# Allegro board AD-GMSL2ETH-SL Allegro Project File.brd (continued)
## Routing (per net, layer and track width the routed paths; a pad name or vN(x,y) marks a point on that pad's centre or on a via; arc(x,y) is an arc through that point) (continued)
3V3: length 198.8
  TOP w0.203: 85.61,53.7 85.65,53.75 U8.A2
  TOP w0.254: 85.59,53.72 C144.1
  TOP w0.279: v1(143.34,22.37) 143.34,21.98 143.04,21.68 U13.15 ; U12.15 v1(143.06,99.44)
  TOP w0.305: v1(120.42,22.91) 120.41,22.93 C124.1 U25.8 ; v1(12.37,40.65) 14.4,38.62 v1(18.74,38.62) ; 85.61,53.7 85.59,53.72 85.59,55.16 86.62,56.19 88.07,56.19 89.82,57.94 107.66,57.94 112.5,62.78 119.25,62.78 120.57,64.1 v1(120.57,65.23) ; v1(118.06,66.67) 118.04,66.69 C115.1 U20.8 ; U3.34 v1(95.11,111.23)
  TOP w0.356: v2(75.69,93.98) P3.B13 P3.B14 ; v1(95.11,111.23) C111.1 ; v1(72.06,17.88) 71.1,17.88 C156.1
  TOP w0.483: R45.1 v1(96.1,113.18) ; R56.1 v1(118.06,66.67) ; R38.1 v1(90.04,111.15) ; v1(135.95,64.96) R81.1 R83.1 R80.1 ; R155.1 v1(117.27,21.82) ; R42.1 93.54,112.4 93.37,112.57 92.45,112.57 R40.1 v1(91.71,112.82) ; v1(138.83,54.26) R127.1 R133.1 R184.1 R203.1 R179.1 R183.1 ; R124.1 v1(114.91,65.58) ; R82.1 v1(141.91,62.3) ; v1(120.42,22.91) R69.1
  TOP w0.508: v1(19.5,37.86) v1(19.5,38.62) v1(18.74,38.62) ; v1(19.5,37.86) v1(18.74,37.86) v1(18.74,38.62) ; v1(19.5,37.86) v1(18.74,38.62) ; DS9.A v1(120.66,14.96) ; R248.1 122.7,19.25 v1(121.72,19.25) ; DS6.A v1(105.3,14.96) ; DS10.A v1(128.33,14.96) ; DS8.A v1(112.97,14.96)
  TOP w0.61: D9.2 20.28,79.77 D16.2 23.19,78.74 23.19,78.74 v1(23.32,78.74) ; D25.2 v1(19.29,57.73) ; D19.2 22.33,87.65 v1(23.32,86.66) ; D23.2 v1(19.29,54.58) ; D10.2 20.35,82.92 21.31,81.97 D17.2 v1(23.31,81.35) ; D20.2 v1(19.35,65.6) ; v1(23.32,84.63) 23.18,84.5 D18.2 21.31,85.12 20.35,86.07 D11.2 ; D22.2 19.37,68.75 19.87,68.25 21.31,68.25 ; D7.2 19.44,71.9 19.94,71.4 21.31,71.4 ; 23.32,68.25 21.31,68.25 ; 21.31,68.25 D21.2 ; v1(23.32,76.08) 23.32,76.08 D15.2 ; D8.2 19.21,75.05 19.82,74.44 20.35,74.44 D14.2 23.32,73.47 ; 21.31,71.4 D24.2 ; 21.31,71.4 23.32,71.4 ; D12.2 v1(19.35,89.22)
  TOP w0.889: v1(23.32,86.66) v1(23.32,84.63) 23.32,81.35 v1(23.31,81.35) 23.32,81.35 v1(23.32,78.74) v1(23.32,76.08) v1(23.32,72.31) v1(23.32,69.22) v1(23.32,66.07)
  BOTTOM w0.203: 141.86,55.29 U7.A2 ; v1(72.06,17.88) U22.A3
  BOTTOM w0.305: C147.1 13.18,41.28 R74.1 v1(12.37,40.65) ; 90.04,117.51 C119.1 91.06,117.51 91.22,117.68 U15.8
  BOTTOM w0.483: R48.1 v1(89.92,114.73) ; 141.86,55.29 C143.1 v1(143.56,55.29) ; v1(89.59,117.51) 90.04,117.51
  BOTTOM w0.508: C257.1 v1(64.18,18.08) P9.4 ; 75.69,91.46 v2(75.69,93.98) ; R61.1 R59.1 31.33,24.68 30.16,25.84 R146.1 v1(28.43,25.84) 28.35,25.93 R150.1 v1(27.71,26.7) R147.1 ; R148.1 v1(28.35,19.79) ; C256.1 v1(72.06,17.88)
  BOTTOM w0.762: 75.69,91.46 74.93,90.7 66.35,90.7 64.72,92.33 64.72,101.27 66.33,102.88 v1(66.33,109.01) v1(66.33,109.91)
  vias: v1(48.89,25.54) v1(48.89,24.77) v1(49.65,25.54) v1(49.65,24.77) v1(144.78,19.48) v1(145.06,96.52)
3V3_FT232R: length 18.5
  TOP w0.305: v1(86.51,16.59) 86.78,16.32 C262.1 U24.1 ; U24.4 v1(86.78,12.94)
  TOP w0.356: v1(86.78,12.94) 86.41,12.57 v1(85.67,12.57) 85.66,12.55 85.66,10.68 84.09,9.12 v1(80.91,9.12)
  L5_PWR w0.356: v1(86.51,16.59) 86.51,13.2 v1(86.78,12.94)
  BOTTOM w0.305: U23.1 C258.1 85.45,12.79 v1(85.67,12.57) ; v1(80.91,9.12) 80.91,9.75 ; 80.91,9.75 80.92,9.75 C261.1 ; 80.91,9.75 U23.8
3V3_SFP_RX: length 13.5
  BOTTOM w0.508: 41.2,23.39 39.85,24.74 v1(39.6,24.74) C2.1
  BOTTOM w0.762: 41.2,23.39 42.49,23.39 43.26,22.63 43.26,21.17 43.76,20.66 C254.1
  BOTTOM w0.889: L10.2 47.16,19.31 45.81,20.66 C254.1
3V3_SFP_TX: length 13.7
  BOTTOM w0.508: C3.1 v1(39.6,25.54) 39.89,25.54 40.87,26.52
  BOTTOM w0.762: 40.87,26.52 42.49,26.52 43.26,27.28 43.26,29.15 43.76,29.65 C1.1
  BOTTOM w0.889: C1.1 45.81,29.65 47.16,31.01 L11.2
3V8: length 13.9
  TOP w0.305: v1(30.15,40.64) 30.15,40.61 32.15,38.62 v1(36.52,38.62)
  TOP w0.508: v1(36.52,38.62) v1(36.52,37.86) v1(37.28,37.86) ; v1(36.52,38.62) v1(37.28,37.86) ; v1(36.52,38.62) v1(37.28,38.62) v1(37.28,37.86)
  BOTTOM w0.305: C146.1 30.96,42.21 R229.1 v1(30.15,40.64)
  vias: v1(120.42,117.97) v1(120.42,117.2) v1(121.18,117.97) v1(121.18,117.2)
5V: length 140.7
  TOP w0.254: R109.2 v1(34.24,71.7)
  TOP w0.305: R220.1 45.32,51.33 v1(45.34,51.35) C271.1 46.47,51.35 46.78,51.04 U26.5
  TOP w0.356: R101.1 50.32,57.54 P6.2
  TOP w0.483: R29.1 v1(74.96,106.72) ; R100.1 v1(24.82,90.12) ; R112.1 v1(25.74,85.88)
  TOP w0.508: DS11.A v1(132.53,14.96)
  TOP w0.61: D6.2 v1(21.31,57.44)
  L5_PWR w0.508: 49.5,55.64 P6.2 ; P6.2 49.5,57.8 ; P6.2 48.43,56.72 ; P6.2 50.58,56.72
  BOTTOM w0.254: v1(34.24,71.7) R111.1
  BOTTOM w0.508: v1(39.04,39.8) 39.88,39.8 40.39,39.29 40.39,36.55 42.88,34.06 53.16,34.06 58.67,39.57 83.67,39.57 86.18,37.06 86.18,20.47 90.3,16.36 131.13,16.36 v1(132.53,14.96)
  BOTTOM w0.889: P6.2 50.91,56.72 D1.C
  vias: v1(19.73,44.97) v1(19.73,44.21) v1(20.49,44.97) v1(20.49,44.21) v1(28.62,44.97) v1(28.62,44.21) v1(29.38,44.97) v1(29.38,44.21) v1(31.75,76.15) v1(31.75,75.39) v1(31.75,74.63) v1(31.75,73.86) v1(32.51,76.15) v1(32.51,75.39) v1(32.51,74.63) v1(32.51,73.86) v1(37.51,44.97) v1(37.51,44.21) v1(38.27,44.97) v1(38.27,44.21) v1(46.4,44.97) v1(46.4,44.21) v1(47.16,44.97) v1(47.16,44.21) v1(110.24,95.07) v1(110.24,94.37)
5V_BIAS: length 4.2
  TOP w0.305: U10.13 31.2,84.85 v1(30.99,84.63) 30.67,84.32 C228.1
  TOP w0.483: R93.1 v1(31.03,92.69) ; R110.2 v1(25.74,86.66) ; R96.1 v1(33.15,92.68)
5V_SYNCOUT: length 47.6
  TOP w0.305: U10.2 31.7,89.36 v1(31.7,90.55)
  TOP w0.483: R240.2 v1(42.44,51.05)
  L8_SIG w0.508: v1(42.44,51.05) 37.36,56.13 37.36,64.83 29.44,72.75 29.44,88.29 v1(31.7,90.55)
9V_FB: length 10.9
  TOP w0.305: v1(39.02,52.26) U21.18
  BOTTOM w0.508: v1(44.83,60.02) 39.02,54.21 v1(39.02,52.26)
GND: length 2443
  TOP w0.203: 73.48,17.32 73.76,17.6 v5(73.76,18.08) 73.76,18.64 ; v3(73.15,28.9) 73.15,28.88 ; 87.64,55.09 87.63,55.08
  TOP w0.254: P5.C10 73.78,27.78 73.76,27.76 ; P5.C10 v4(74.1,28.95) P5.D11 74.42,30.17 74.37,30.22 ; P5.C10 P5.C9 ; 89.63,30.23 89.66,30.2 P5.D35 P5.C34 89.02,27.85 88.94,27.76 ; v2(88.13,95.58) P3.C33 88.39,94.57 88.39,94.57 ; 80.13,26.41 P5.B20 80.13,27.36 80.14,27.37 ; 80.13,26.41 v2(80.45,26.41) ; 80.13,26.41 79.82,26.41 P5.A19 79.5,25.31 ; 83.25,27.94 83.31,28 P5.C25 v2(83.63,28.95) P5.D26 83.94,30.06 83.92,30.09 ; 83.25,27.94 83.66,27.94 83.7,27.9 ; 83.25,27.94 v2(82.37,27.94) 82.37,27.39 v2(82.36,27.37) P5.B23 v2(81.72,26.41) P5.A22 ; 90.93,93.05 91.18,93.05 v2(91.24,92.99) P3.A37 ; 90.93,93.05 P3.A37 ; 90.93,93.05 89.66,93.05 ; P5.B8 72.51,27.46 72.51,27.47 ; P5.B8 v3(72.83,26.41) P5.A9 ; P5.B8 P5.B7 ; P3.A57 v2(103.63,91.96) ; P3.A57 P3.A58 ; P3.A57 P3.B56 ; P3.B48 v2(97.91,94.09) ; P3.B48 P3.A49 ; P3.B48 P3.B47 ; P3.A37 90.93,92.04 ; P5.D43 94.74,29.43 v3(94.74,28.96) 94.74,28.95 P5.C43 94.74,27.91 94.73,27.91 ; P3.C37 v2(90.93,94.6) ; 89.66,93.94 P3.B35 89.66,93.05 ; P5.C5 P5.C6 71.25,28.48 v4(71.25,28.9) 71.53,28.9 P5.D7 ; v3(97.28,29.92) 97.28,29.92 P5.D47 ; P5.A9 73.05,25.84 73.05,25.35 v4(73.07,25.34) ; P5.A9 P5.A10 ; P3.C54 v2(101.72,94.5) ; P3.C54 P3.D55 ; P3.C54 P3.C53 ; 72.49,94.55 72.51,94.57 P3.C8 P3.D9 v2(73.15,96.63) ; 85.24,25.34 85.21,25.37 P5.A28 v2(85.53,26.41) P5.B29 85.85,27.46 85.87,27.47 ; v2(73.15,94.09) P3.B9 P3.A8 v2(72.51,91.96) ; v2(76.35,91.95) 76.32,91.98 P3.A14 P3.B15 v3(76.96,93.99) ; 82.04,92.96 82.04,92.96 P3.B23 ; 82.04,92.96 v2(80.77,92.96) P3.A21 ; 82.04,92.96 83.95,92.96 ; P5.A10 73.78,25.44 73.61,25.27 ; P5.A10 v2(74.1,26.41) P5.B11 74.42,27.34 74.21,27.54 ; 103.7,25.22 103.63,25.28 P5.A57 ; 78.23,27.49 P5.B17 v4(77.91,26.41) P5.A16 77.59,25.55 v4(77.77,25.37) ; 96.01,26.41 94.75,26.41 94.74,26.42 ; 96.01,26.41 v2(96.33,26.41) 97.12,26.41 97.28,26.57 97.28,26.57 P5.B47 97.28,27.41 97.36,27.49 ; 96.01,26.41 96.01,26.41 P5.A45 96.01,25.37 95.99,25.35 ; P3.A49 v2(98.55,91.96) ; P3.A49 P3.A50 ; P5.C9 v3(73.15,28.9) 72.87,28.9 P5.D8 ; P5.C9 73.15,28.88 ; P5.C9 73.15,27.73 73.17,27.71 ; P3.B39 92.2,93.95 v2(92.04,94.1) ; 83.94,92.96 P3.A26 v2(83.94,91.96) ; 83.95,92.96 84.25,92.96 84.58,93.29 P3.B27 v2(84.58,94.09) ; 90.94,25.23 90.93,25.24 P5.A37 P5.B38 91.56,27.5 91.67,27.6 ; 94.74,26.42 P5.A43 94.74,25.38 94.66,25.3 ; 94.74,26.42 P5.B43 ; 94.74,26.42 94.73,26.41 93.47,26.41 ; v2(96.64,94.5) P3.C46 P3.D47 ; P5.D8 72.51,30.1 72.51,30.11 ; P5.D8 P5.D7 ; P3.A54 v2(101.72,91.96) ; P3.A54 P3.A53 ; P3.A54 P3.B55 ; P5.B7 71.88,27.44 71.89,27.45 ; P5.B7 71.53,26.36 v3(71.25,26.36) 71.24,26.35 P5.A6 ; P3.D43 94.74,96.58 v2(94.69,96.64) ; P5.A5 v3(70.29,26.41) P5.B4 P5.B3 ; P5.A5 70.61,25.23 ; P5.A5 P5.A6 ; v4(75.37,27.99) P5.C13 P5.D14 v2(76.32,29.86) ; v2(104.9,96.63) P3.D59 P3.C58 ; v2(74.24,91.94) 74.42,92.12 P3.A11 P3.B12 v2(75.05,93.99) ; P3.C53 v2(101.09,94.5) ; P3.C53 P3.D52 ; v2(79.5,96.63) P3.D19 79.5,95.81 79.75,95.56 80.77,95.56 ; P3.B51 P3.B52 ; P3.B51 P3.A50 ; P3.B51 v2(99.82,94.09) ; P3.B52 v2(100.45,94.09) ; P3.B52 P3.A53 ; P3.A50 v2(99.18,91.96) ; P5.C1 P5.C2 v4(69.02,28.95) P5.D3 ; 103.59,27.88 103.63,27.92 P5.C57 103.63,28.7 103.38,28.96 102.69,28.96 102.36,29.29 P5.D55 102.36,30.05 102.19,30.22 ; 83.91,27.53 83.94,27.5 P5.B26 v2(83.63,26.41) P5.A25 83.31,25.24 83.32,25.23 ; 98.54,27.86 98.55,27.86 P5.C49 v2(98.87,28.95) ; P3.C49 v2(98.55,94.5) ; P3.C49 P3.C50 ; P3.C49 P3.D48 ; 87.08,27.66 87.12,27.7 P5.C31 87.47,29 v3(87.75,29) 87.75,29.42 P5.D32 87.75,30.04 87.82,30.11 ; P3.C57 v2(103.63,94.5) ; P3.C57 P3.D56 ; P3.C57 P3.C58 ; P3.C50 v2(99.18,94.5) ; P3.C50 P3.D51 ; P3.D51 v2(99.82,96.63) ; P3.D51 P3.D52 ; P5.D3 69.34,30.13 69.31,30.16 ; P5.D3 P5.D4 69.97,29.98 70.06,30.06 ; P3.D52 v2(100.45,96.63) ; v2(96.01,91.96) P3.A45 P3.A46 ; P3.C29 v2(85.85,94.6) ; P5.D7 71.88,30.04 71.87,30.05 ; P5.A53 v2(101.41,25.45) ; 89.69,27.54 89.66,27.5 P5.B35 P5.A34 89.02,25.3 89.16,25.17 ; P5.C45 96.01,27.99 v3(95.99,27.97) ; v2(70.61,91.96) P3.A5 P3.B6 v2(71.24,93.99) ; P3.D56 v2(102.99,96.63) ; P3.D56 P3.D55 ; P5.B51 v3(100.31,27.63) 101.09,27.63 v3(101.09,27.64) 102.06,27.64 102.36,27.33 P5.B55 ; 74.36,94.54 74.42,94.6 P3.C11 P3.D12 v2(75.05,96.71) ; U8.A3 86.82,54.15 86.7,54.27 ; P3.A58 P3.B59 v2(104.9,93.99) ; P3.A58 v2(104.26,91.96) ; 69.37,94.24 69.34,94.2 P3.B3 P3.A2 v2(68.7,91.96) ; P3.D47 P3.D48 ; P3.D47 v2(97.28,96.63) ; P3.D48 v2(97.91,96.63) ; P3.D55 v2(102.36,96.63) ; P5.A6 71.24,25.39 ; P3.D27 v2(84.58,96.63) ; P3.A46 v2(96.64,91.96) ; P3.A46 P3.B47 ; P3.C2 68.7,94.52 68.74,94.49 ; P3.C2 P3.C1 v2(68.07,94.6) ; P3.C2 P3.D3 69.34,96.62 69.3,96.67 ; v2(81.09,27.99) P5.C22 P5.D23 82.04,29.94 82.17,30.07 ; P3.D35 v2(89.66,96.63) ; v2(76.96,96.63) P3.D15 P3.C14 v2(76.32,94.6) ; P3.C58 v2(104.26,94.5) ; v2(79.82,27.99) P5.C19 v2(79.82,28.95) P5.D20 80.13,30.01 80.07,30.08 ; 85.83,30.03 85.85,30.01 P5.D29 v2(85.53,28.95) P5.C28 85.21,27.75 85.15,27.69 ; 87.29,25.24 87.12,25.41 P5.A31 v2(87.44,26.41) P5.B32 87.75,27.65 87.84,27.73 ; P3.B56 v2(102.99,94.09) ; P3.B56 P3.B55 ; 80.77,95.56 81.79,95.56 82.04,95.81 P3.D23 ; 80.77,95.56 P3.C21 ; P3.D39 v2(92.2,96.63) ; 68.7,25.22 68.7,25.23 P5.A2 P5.A1 68.07,25.33 68.02,25.27 ; 93.44,30.16 93.47,30.13 P5.D41 P5.C40 92.83,27.62 92.84,27.61 ; P3.B31 v2(87.12,94.09) ; P5.A49 v2(98.87,25.45) ; 70.6,94.53 70.61,94.55 P3.C5 P3.D6 v2(71.24,96.63) ; P3.B47 v2(97.28,94.09) ; 93.47,26.41 93.09,26.41 92.83,26.16 P5.A40 92.83,25.1 92.78,25.05 ; 93.47,26.41 P5.B41 93.47,27.45 93.33,27.58 ; 89.66,93.05 88.9,93.05 P3.A33 88.39,91.89 88.35,91.85 ; P3.B55 v2(102.36,94.09) ; P3.C25 v2(83.31,94.6) ; P3.B43 94.74,94.04 v2(94.7,94.09) ; v3(76.32,27.67) 76.32,27.67 P5.B14 v2(76.01,26.41) P5.A13 75.69,25.49 v2(75.47,25.26) ; 90.73,27.8 90.93,27.99 P5.C37 P5.D38 91.56,30.18 91.57,30.18 ; v2(78.86,91.96) P3.A18 P3.B19 ; P3.A53 v2(101.09,91.96) ; 93.47,91.84 P3.A41 ; 78.24,30.09 78.23,30.08 P5.D17 v2(77.91,28.95) P5.C16 77.59,27.67 v3(77.6,27.67) ; P3.D31 v2(87.12,96.63) ; P3.C41 v2(93.47,94.5) ; P5.D51 v3(99.82,29.92) 99.82,29.92 P5.D51
  TOP w0.305: C151.1 v2(106.55,108.33) ; C148.1 106.55,102.39 v2(106.25,102.69) ; 119.08,67.23 C115.2 C114.2 119.09,67.83 ; P5.A2 v3(69.02,26.41) P5.B3 ; U19.9 136.22,59.62 v1(135.97,59.87) ; 121.39,23.42 C124.2 C123.2 121.4,24.02
  TOP w0.356: 80.77,92.05 80.77,92.05 P3.A21 ; P5.C53 101.09,27.64 v3(101.09,27.64) ; P3.C17 v2(78.23,94.6) ; P3.D23 v2(82.04,96.63) ; C111.2 95.11,112.84
  TOP w0.406: 90.68,111.63 91.09,111.22 R39.2 R204.2 91.65,111.78 91.26,112.17 ; 52.29,51.05 R50.2 51.55,51.04 R51.2 50.09,51.04 v1(50.09,51.04) U26.2
  TOP w0.483: R97.2 v1(32.36,92.69) ; R43.1 v1(96.9,113.11) ; 134.72,64.95 134.72,64.95 R114.2 ; Y3.2 89.42,107.29 v1(89.79,107.29) C108.1 ; R99.2 v1(26.44,91.03) ; C227.2 v1(23.88,89.16) ; R237.2 v1(25.74,87.45) ; Y3.4 v1(87.98,104.6) 90.17,104.6 C107.2 ; R94.2 v1(30.25,92.69)
  TOP w0.508: P1.GND8 142.05,85.82 ; P1.GND8 142.05,82.61 ; P1.GND8 141.3,84.22 ; P1.GND8 142.8,84.22 ; J2.4 63.5,104.75 ; J2.4 64.77,103.48 ; J2.4 62.23,103.48 ; J2.4 63.5,102.21 ; 124.75,12.29 R66.2 ; R66.2 125.25,12.83 ; R66.2 124.75,13.36 ; 56.55,18.3 R251.2 ; R251.2 56.55,19.55 ; R251.2 55.98,18.92 ; P2.GND7 142.05,37.39 ; P2.GND7 141.3,35.78 ; P2.GND7 142.05,34.18 ; P2.GND7 142.8,35.78 ; P7.3 48.34,90.83 ; P7.3 48.34,89.33 ; P7.3 46.71,90.08 ; P7.3 49.96,90.08 ; 114.71,111.95 C225.2 ; C225.2 115.87,111.95 ; C225.2 115.29,111.4 ; 117.3,46.69 R176.2 116.73,46.06 ; 135.84,102.21 J3.4 ; J3.4 135.84,104.75 ; J3.4 134.57,103.48 ; J3.4 137.11,103.48 ; R85.2 89.18,55.78 ; R85.2 88.65,55.29 ; R85.2 89.71,55.29 ; C91.2 141.33,27.37 ; C91.2 142.38,26.47 ; C91.2 140.27,26.47 ; 138.1,91.94 C28.2 ; C28.2 139.15,91.03 ; C28.2 140.21,91.94 ; P7.11 49.96,82.08 ; P7.11 48.34,82.83 ; P7.11 48.34,81.33 ; P7.11 46.71,82.08 ; 122.72,113.39 C233.2 122.18,113.98 ; 2.93,51.61 P13.2 ; P13.2 5.09,51.61 ; P13.2 4.01,50.53 ; P13.2 4.01,52.69 ; 137.17,15.7 C89.2 ; C89.2 137.17,17.81 ; C89.2 136.27,16.76 ; 120.94,75.64 C22.2 121.84,76.69 ; R247.2 69.07,91.45 ; R247.2 69.64,90.82 ; R247.2 69.07,90.2 ; 109.54,32.05 R178.2 110.04,32.59 ; C88.2 139.99,26.47 ; C88.2 137.89,26.47 ; C88.2 138.94,27.37 ; 114.28,82.65 R2.1 ; R2.1 115.17,82.55 ; R2.1 115.07,83.44 ; R2.1 114.18,83.54 ; 117.28,49.07 C155.2 116.73,48.49 ; 53.55,56.26 R104.2 53.06,56.79 ; J1.5 80.01,103.48 ; J1.5 77.47,103.48 ; J1.5 78.74,104.75 ; J1.5 78.74,102.21 ; C65.2 120.94,44.62 ; C65.2 121.84,43.56 ; C65.2 120.94,42.51 ; 46.71,88.08 P7.5 ; P7.5 49.96,88.08 ; P7.5 48.34,87.33 ; P7.5 48.34,88.83 ; 144.5,37.18 P2.GND5 ; P2.GND5 144.5,38.68 ; P2.GND5 146.41,37.93 ; P2.GND5 142.6,37.93 ; C30.2 141.54,104.41 ; C30.2 140.48,103.51 ; C30.2 142.59,103.51 ; 109.41,19 R199.2 108.92,19.53 ; 58.42,102.21 J2.5 ; J2.5 57.15,103.48 ; J2.5 58.42,104.75 ; J2.5 59.69,103.48 ; R68.2 122.21,13.36 ; R68.2 122.71,12.83 ; R68.2 122.21,12.29 ; Y4.2 100.4,117.61 ; Y4.2 99.4,116.6 ; Y4.2 101.41,116.6 ; Y4.2 100.4,115.6 ; Q6.2 108.02,16.5 ; Q6.2 108.97,15.74 ; Q6.2 107.06,15.74 ; Q6.2 108.02,14.98 ; 137.48,77.72 P1.GND2 ; P1.GND2 138.75,76.45 ; P1.GND2 138.75,78.99 ; C7.2 120.94,86.04 ; C7.2 121.84,84.99 ; C7.2 120.94,83.94 ; P13.6 5.09,56.69 ; P13.6 4.01,57.77 ; P13.6 4.01,55.61 ; P13.6 2.93,56.69 ; 57.07,15.05 R149.2 57.61,15.54 ; 131.31,59.59 C235.2 130.81,60.12 ; 60.91,13.2 Q2.2 ; Q2.2 60.91,15.1 ; Q2.2 60.15,14.15 ; Q2.2 61.67,14.15 ; P7.9 49.96,84.08 ; P7.9 48.34,84.83 ; P7.9 46.71,84.08 ; P7.9 48.34,83.33 ; 142.14,13.08 R219.2 142.64,12.55 ; 33.34,113.17 R225.2 ; R225.2 34.58,113.17 ; R225.2 33.96,112.59 ; P6.1 49.5,55.26 ; P6.1 48.43,54.18 ; P6.1 50.58,54.18 ; P6.1 49.5,53.1 ; 115.52,102.21 J4.5 ; J4.5 116.79,103.48 ; J4.5 115.52,104.75 ; J4.5 114.25,103.48 ; C117.2 109.14,114 ; C117.2 108.61,113.5 ; C117.2 109.68,113.5 ; R169.2 116.53,88.39 ; P1.GND5 146.41,82.07 ; P1.GND5 142.6,82.07 ; P1.GND5 144.5,81.32 ; P1.GND5 144.5,82.82 ; Q12.2 115.71,16.5 ; Q12.2 114.76,15.74 ; Q12.2 116.66,15.74 ; Q12.2 115.71,14.98 ; C112.2 112.32,115.29 ; C112.2 111.79,114.79 ; C112.2 112.85,114.79 ; J2.3 63.5,109.83 ; J2.3 63.5,107.29 ; J2.3 62.23,108.56 ; J2.3 64.77,108.56 ; P2.GND2 138.75,34.85 ; P2.GND2 137.48,33.58 ; P2.GND2 138.75,32.31 ; 29.83,21.14 30.89,21.14 ; 30.89,21.14 30.89,20.5 ; 30.89,21.14 P4.10 ; P2.GND8 142.8,40.08 ; P2.GND8 141.3,40.08 ; P2.GND8 142.05,38.48 ; P2.GND8 142.05,41.68 ; 141.54,91.03 C29.2 ; C29.2 140.49,91.94 ; C29.2 142.6,91.94 ; 142.05,43.35 P2.GND10 142.05,41.8 ; P13.4 4.01,55.23 ; P13.4 4.01,53.07 ; P13.4 2.93,54.15 ; P13.4 5.09,54.15 ; 39.7,20.7 39.7,21.54 ; 39.7,21.54 41.05,21.54 ; 39.7,21.54 v1(39.6,21.54) ; 83.82,102.21 J1.4 ; J1.4 82.55,103.48 ; J1.4 85.09,103.48 ; J1.4 83.82,104.75 ; R95.2 29.96,92.59 ; R95.2 28.56,92.59 ; R95.2 29.26,93.15 ; R95.2 29.26,92.03 ; 82.55,108.56 J1.3 ; J1.3 85.09,108.56 ; J1.3 83.82,109.83 ; J1.3 83.82,107.29 ; P1.GND1 145.15,78.99 ; P1.GND1 146.42,77.72 ; P1.GND1 145.15,76.45 ; 122.18,111.71 C234.2 122.72,112.29 ; 97.18,97.89 C96.2 97.59,98.35 ; J3.3 135.84,109.83 ; J3.3 137.11,108.56 ; J3.3 135.84,107.29 ; J3.3 134.57,108.56 ; 119.33,103.48 J4.4 ; J4.4 120.6,102.21 ; J4.4 120.6,104.75 ; J4.4 121.87,103.48 ; C90.2 143.07,17.81 ; C90.2 143.97,16.76 ; C90.2 143.07,15.7 ; 118.18,111.33 R227.2 ; R227.2 118.68,110.79 ; R227.2 118.68,111.86 ; 115.52,107.29 J4.2 ; J4.2 114.25,108.56 ; J4.2 116.79,108.56 ; J4.2 115.52,109.83 ; R64.2 129.83,13.36 ; R64.2 130.33,12.83 ; R64.2 129.83,12.29 ; 114.53,114.79 C109.2 115.06,115.29 ; 77.47,108.56 J1.2 ; J1.2 78.74,107.29 ; J1.2 78.74,109.83 ; J1.2 80.01,108.56 ; 46.71,92.08 P7.1 ; P7.1 49.96,92.08 ; P7.1 48.34,91.33 ; P7.1 48.34,92.83 ; 145.32,18.36 R165.2 144.82,17.83 ; v1(128.27,59.34) R118.2 128.99,59.33 R116.2 ; C4.2 121.84,87.37 ; C4.2 120.94,88.42 ; C4.2 120.94,86.32 ; 141.3,79.92 P1.GND7 ; P1.GND7 142.8,79.92 ; P1.GND7 142.05,78.32 ; P1.GND7 142.05,81.52 ; P2.GND6 139.75,38.68 ; P2.GND6 141.5,37.93 ; P2.GND6 138,37.93 ; P2.GND6 139.75,37.18 ; 128.99,57.89 R116.2 ; R116.2 128.49,58.42 ; R23.1 115.17,38.42 ; R23.1 114.28,38.51 ; R23.1 114.18,39.4 ; R23.1 115.07,39.3 ; Q13.2 124.36,15.74 ; Q13.2 123.41,16.5 ; Q13.2 123.41,14.98 ; Q13.2 122.46,15.74 ; P2.GND3 146.42,42.28 ; P2.GND3 145.15,43.55 ; P2.GND3 145.15,41.01 ; J4.3 121.87,108.56 ; J4.3 120.6,109.83 ; J4.3 119.33,108.56 ; J4.3 120.6,107.29 ; 2.93,59.23 P13.8 ; P13.8 4.01,58.15 ; P13.8 5.09,59.23 ; P13.8 4.01,60.31 ; 138,82.07 P1.GND6 ; P1.GND6 139.75,82.82 ; P1.GND6 139.75,81.32 ; P1.GND6 141.5,82.07 ; C83.2 121.84,31.88 ; C83.2 120.94,30.83 ; C83.2 120.94,32.93 ; v1(39.6,23.94) 40.97,23.94 ; 129.49,103.48 J3.5 ; J3.5 130.76,104.75 ; J3.5 132.03,103.48 ; J3.5 130.76,102.21 ; 138.75,41.01 P2.GND4 ; P2.GND4 138.75,43.55 ; P2.GND4 137.48,42.28 ; P1.GND3 145.15,87.69 ; P1.GND3 145.15,85.15 ; P1.GND3 146.42,86.42 ; Q3.2 100.32,16.5 ; Q3.2 99.37,15.74 ; Q3.2 101.27,15.74 ; Q3.2 100.32,14.98 ; 48.34,79.33 P7.13 ; P7.13 48.34,80.83 ; P7.13 49.96,80.08 ; P7.13 46.71,80.08 ; 115.11,4.39 R67.2 115.65,3.9 ; 117.31,115.58 C118.2 ; C118.2 117.31,117.08 ; C118.2 118.03,116.33 ; 116.61,19.53 R201.2 117.11,19 ; 30.89,28.34 P4.1 ; 30.89,28.34 29.87,28.34 ; 30.89,28.34 30.89,28.98 ; 44.07,106.68 S12.3 ; S12.3 46.86,106.68 ; S12.3 45.47,105.28 ; S12.3 45.47,108.08 ; 58.42,107.29 J2.2 ; J2.2 57.15,108.56 ; J2.2 58.42,109.83 ; J2.2 59.69,108.56 ; C27.2 140.2,103.51 ; C27.2 138.1,103.51 ; C27.2 139.15,104.41 ; 30.92,115.42 31.5,115.42 31.5,114.8 ; 145.15,32.31 P2.GND1 ; P2.GND1 146.42,33.58 ; P2.GND1 145.15,34.85 ; 121.84,80.23 C152.2 120.94,81.28 ; 131.35,15.74 R206.2 130.82,16.23 ; 70.51,18.89 C156.2 71.09,19.44 ; 23.88,87.94 C227.2 23.35,88.45 ; C15.2 121.84,82.61 ; C15.2 120.94,81.56 ; C15.2 120.94,83.67 ; 48.34,85.33 P7.7 ; P7.7 46.71,86.08 ; P7.7 49.96,86.08 ; P7.7 48.34,86.83 ; 120.94,37.44 C154.2 121.84,36.39 ; 105.03,3.9 R63.2 104.5,4.39 ; P13.1 7.63,51.61 ; P13.1 6.55,50.53 ; P13.1 5.47,51.61 ; P13.1 6.55,52.69 ; 137.48,86.42 P1.GND4 ; P1.GND4 138.75,85.15 ; P1.GND4 138.75,87.69 ; v1(39.6,26.34) 41.1,26.34 ; P8.1 6.82,98.37 ; P8.1 4.41,98.37 ; P8.1 5.61,97.17 ; P8.1 5.61,99.58 ; 144.25,93.95 R157.2 ; R157.2 143.71,94.44 ; R157.2 144.78,94.44 ; 67.31,104.63 R30.2 ; R30.2 66.78,105.12 ; R30.2 67.84,105.12 ; R65.2 127.79,12.83 ; R65.2 127.29,12.29 ; R65.2 127.29,13.36 ; 142.05,34.07 P2.GND9 142.05,32.52 ; 122.1,73.12 R171.2 121.56,73.61 ; 130.76,107.29 J3.2 ; J3.2 129.49,108.56 ; J3.2 132.03,108.56 ; J3.2 130.76,109.83 ; C76.2 121.84,38.79 ; C76.2 120.94,37.74 ; C76.2 120.94,39.84 ; 115.89,92.33 C153.2 116.44,91.74 ; C68.2 120.94,42.25 ; C68.2 121.84,41.19 ; C68.2 120.94,40.14 ; 142.05,76.65 P1.GND9 142.05,78.2 ; D25.1 v1(19.29,56.73) ; 39.7,28.74 v1(39.6,28.74) ; 39.7,28.74 39.7,29.54 ; 39.7,28.74 41,28.74 ; 30.41,115.42 R222.2 29.84,114.8 ; R190.2 v1(91.74,101.74) ; 101.72,19 R152.2 101.22,19.53 ; 142.05,87.48 P1.GND10 142.05,85.93
  L2_GND w0.203: 73.75,18.82 73.76,18.81 v5(73.76,18.08) 73.76,17.57 73.69,17.5
  L2_GND w0.508: 78.74,102.21 J1.5 ; J1.5 77.47,103.48 ; J1.5 78.74,104.75 ; J1.5 80.01,103.48 ; 4.6,30.99 M4.GND12 ; M4.GND12 4.6,33.15 ; M4.GND12 3.52,32.07 ; M4.GND12 5.68,32.07 ; 31.08,32.07 M4.GND16 ; M4.GND16 33.12,32.07 ; M4.GND16 32.1,33.08 ; M4.GND16 32.1,31.05 ; 36.08,17.82 M4.GND5 ; M4.GND5 37.1,16.8 ; M4.GND5 37.1,18.83 ; M4.GND5 38.12,17.82 ; 138.75,41.01 P2.GND4 ; P2.GND4 138.75,43.55 ; P2.GND4 140.02,42.28 ; P2.GND4 137.48,42.28 ; 143.88,42.28 P2.GND3 ; P2.GND3 146.42,42.28 ; P2.GND3 145.15,41.01 ; P2.GND3 145.15,43.55 ; M4.GND18 37.1,33.08 ; M4.GND18 37.1,31.05 ; M4.GND18 36.08,32.07 ; M4.GND18 38.12,32.07 ; 143.88,77.72 P1.GND1 ; P1.GND1 145.15,78.99 ; P1.GND1 146.42,77.72 ; P1.GND1 145.15,76.45 ; M4.GND17 34.6,33.02 ; M4.GND17 35.55,32.07 ; M4.GND17 33.65,32.07 ; 45.47,105.28 S12.3 ; S12.3 45.47,108.08 ; S12.3 46.86,106.68 ; S12.3 44.07,106.68 ; 8.52,17.82 M4.GND10 ; M4.GND10 10.68,17.82 ; M4.GND10 9.6,16.74 ; M4.GND10 9.6,18.9 ; J3.5 132.03,103.48 ; J3.5 129.49,103.48 ; J3.5 130.76,104.75 ; J3.5 130.76,102.21 ; J3.4 137.11,103.48 ; J3.4 135.84,102.21 ; J3.4 134.57,103.48 ; J3.4 135.84,104.75 ; P2.GND2 140.02,33.58 ; P2.GND2 138.75,32.31 ; P2.GND2 137.48,33.58 ; P2.GND2 138.75,34.85 ; P1.GND4 140.02,86.42 ; P1.GND4 137.48,86.42 ; P1.GND4 138.75,85.15 ; P1.GND4 138.75,87.69 ; 28.52,17.82 M4.GND7 ; M4.GND7 30.68,17.82 ; M4.GND7 29.6,16.74 ; M4.GND7 29.6,18.9 ; 4.41,98.37 P8.1 ; P8.1 6.82,98.37 ; P8.1 5.61,99.58 ; P8.1 5.61,97.17 ; J2.4 64.77,103.48 ; J2.4 63.5,104.75 ; J2.4 63.5,102.21 ; J2.4 62.23,103.48 ; J4.4 120.6,104.75 ; J4.4 120.6,102.21 ; J4.4 119.33,103.48 ; J4.4 121.87,103.48 ; M4.GND6 32.1,18.83 ; M4.GND6 32.1,16.8 ; M4.GND6 33.12,17.82 ; M4.GND6 31.08,17.82 ; P2.GND1 145.15,34.85 ; P2.GND1 143.88,33.58 ; P2.GND1 145.15,32.31 ; P2.GND1 146.42,33.58 ; M4.GND9 19.6,18.9 ; M4.GND9 18.52,17.82 ; M4.GND9 19.6,16.74 ; M4.GND9 20.68,17.82 ; 27.4,16.8 M4.GND8 ; M4.GND8 26.38,17.82 ; M4.GND8 27.4,18.83 ; M4.GND8 28.42,17.82 ; M4.GND4 39.6,18.9 ; M4.GND4 38.52,17.82 ; M4.GND4 39.6,16.74 ; M4.GND4 40.68,17.82 ; M4.GND20 24.6,22.07 ; M4.GND20 25.68,20.99 ; M4.GND20 24.6,19.91 ; M4.GND20 23.52,20.99 ; 115.52,107.29 J4.2 ; J4.2 115.52,109.83 ; J4.2 114.25,108.56 ; J4.2 116.79,108.56 ; M4.GND13 15.68,32.07 ; M4.GND13 14.6,33.15 ; M4.GND13 13.52,32.07 ; M4.GND13 14.6,30.99 ; 48.43,54.18 P6.1 ; P6.1 49.5,53.1 ; P6.1 49.5,55.26 ; P6.1 50.58,54.18 ; 23.52,26.39 M4.GND19 ; M4.GND19 24.6,27.47 ; M4.GND19 24.6,25.31 ; M4.GND19 25.68,26.39 ; 130.76,107.29 J3.2 ; J3.2 130.76,109.83 ; J3.2 129.49,108.56 ; J3.2 132.03,108.56 ; 24.6,30.99 M4.GND14 ; M4.GND14 23.52,32.07 ; M4.GND14 25.68,32.07 ; M4.GND14 24.6,33.15 ; 4.01,55.61 P13.6 ; P13.6 5.09,56.69 ; P13.6 2.93,56.69 ; P13.6 4.01,57.77 ; 120.6,107.29 J4.3 ; J4.3 120.6,109.83 ; J4.3 121.87,108.56 ; J4.3 119.33,108.56 ; 83.82,102.21 J1.4 ; J1.4 85.09,103.48 ; J1.4 82.55,103.48 ; J1.4 83.82,104.75 ; P1.GND2 140.02,77.72 ; P1.GND2 138.75,76.45 ; P1.GND2 138.75,78.99 ; P1.GND2 137.48,77.72 ; 62.23,108.56 J2.3 ; J2.3 64.77,108.56 ; J2.3 63.5,107.29 ; J2.3 63.5,109.83 ; 41.7,19.12 M4.GND3 ; M4.GND3 42.72,20.14 ; M4.GND3 40.68,20.14 ; M4.GND3 41.7,21.15 ; 40.68,29.74 M4.GND1 ; M4.GND1 42.72,29.74 ; M4.GND1 41.7,30.75 ; M4.GND1 41.7,28.72 ; P13.8 5.09,59.23 ; P13.8 4.01,60.31 ; P13.8 4.01,58.15 ; P13.8 2.93,59.23 ; P13.1 6.55,52.69 ; P13.1 6.55,50.53 ; P13.1 5.47,51.61 ; P13.1 7.63,51.61 ; P13.4 4.01,55.23 ; P13.4 4.01,53.07 ; P13.4 5.09,54.15 ; P13.4 2.93,54.15 ; M4.GND2 41.7,25.95 ; M4.GND2 40.68,24.94 ; M4.GND2 41.7,23.92 ; M4.GND2 42.72,24.94 ; 83.82,107.29 J1.3 ; J1.3 82.55,108.56 ; J1.3 83.82,109.83 ; J1.3 85.09,108.56 ; J4.5 115.52,104.75 ; J4.5 116.79,103.48 ; J4.5 114.25,103.48 ; J4.5 115.52,102.21 ; J2.5 58.42,104.75 ; J2.5 58.42,102.21 ; J2.5 57.15,103.48 ; J2.5 59.69,103.48 ; J3.3 135.84,109.83 ; J3.3 134.57,108.56 ; J3.3 135.84,107.29 ; J3.3 137.11,108.56 ; J2.2 59.69,108.56 ; J2.2 58.42,107.29 ; J2.2 57.15,108.56 ; J2.2 58.42,109.83 ; M4.GND11 4.6,24.57 ; M4.GND11 4.6,22.41 ; M4.GND11 3.52,23.49 ; M4.GND11 5.68,23.49 ; P1.GND3 146.42,86.42 ; P1.GND3 143.88,86.42 ; P1.GND3 145.15,87.69 ; P1.GND3 145.15,85.15 ; J1.2 78.74,109.83 ; J1.2 78.74,107.29 ; J1.2 77.47,108.56 ; J1.2 80.01,108.56 ; 26.38,32.07 M4.GND15 ; M4.GND15 28.42,32.07 ; M4.GND15 27.4,33.08 ; M4.GND15 27.4,31.05 ; 2.93,51.61 P13.2 ; P13.2 4.01,52.69 ; P13.2 4.01,50.53 ; P13.2 5.09,51.61
  L3_SIG w0.203: 73.76,18.52 v5(73.76,18.08) 73.76,17.53
  L3_SIG w0.508: 83.82,102.21 J1.4 ; J1.4 83.82,104.75 ; J1.4 82.55,103.48 ; J1.4 85.09,103.48 ; 4.41,98.37 P8.1 ; P8.1 5.61,97.17 ; P8.1 5.61,99.58 ; P8.1 6.82,98.37 ; P13.6 5.09,56.69 ; P13.6 4.01,57.77 ; P13.6 4.01,55.61 ; P13.6 2.93,56.69 ; 23.52,32.07 M4.GND14 ; M4.GND14 24.6,33.15 ; M4.GND14 25.68,32.07 ; M4.GND14 24.6,30.99 ; J4.4 121.87,103.48 ; J4.4 120.6,104.75 ; J4.4 120.6,102.21 ; J4.4 119.33,103.48 ; J3.5 132.03,103.48 ; J3.5 130.76,102.21 ; J3.5 130.76,104.75 ; J3.5 129.49,103.48 ; 8.52,17.82 M4.GND10 ; M4.GND10 10.68,17.82 ; M4.GND10 9.6,16.74 ; M4.GND10 9.6,18.9 ; 137.48,42.28 P2.GND4 ; P2.GND4 140.02,42.28 ; P2.GND4 138.75,41.01 ; P2.GND4 138.75,43.55 ; J3.4 135.84,104.75 ; J3.4 135.84,102.21 ; J3.4 137.11,103.48 ; J3.4 134.57,103.48 ; S12.3 45.47,108.08 ; S12.3 45.47,105.28 ; S12.3 44.07,106.68 ; S12.3 46.86,106.68 ; M4.GND11 5.68,23.49 ; M4.GND11 3.52,23.49 ; M4.GND11 4.6,22.41 ; M4.GND11 4.6,24.57 ; 4.01,50.53 P13.2 ; P13.2 2.93,51.61 ; P13.2 5.09,51.61 ; P13.2 4.01,52.69 ; M4.GND5 38.12,17.82 ; M4.GND5 36.08,17.82 ; M4.GND5 37.1,18.83 ; M4.GND5 37.1,16.8 ; 18.52,17.82 M4.GND9 ; M4.GND9 20.68,17.82 ; M4.GND9 19.6,16.74 ; M4.GND9 19.6,18.9 ; M4.GND16 33.12,32.07 ; M4.GND16 32.1,31.05 ; M4.GND16 32.1,33.08 ; M4.GND16 31.08,32.07 ; 145.15,41.01 P2.GND3 ; P2.GND3 143.88,42.28 ; P2.GND3 145.15,43.55 ; P2.GND3 146.42,42.28 ; 14.6,30.99 M4.GND13 ; M4.GND13 15.68,32.07 ; M4.GND13 13.52,32.07 ; M4.GND13 14.6,33.15 ; 62.23,108.56 J2.3 ; J2.3 63.5,107.29 ; J2.3 63.5,109.83 ; J2.3 64.77,108.56 ; M4.GND12 5.68,32.07 ; M4.GND12 4.6,33.15 ; M4.GND12 4.6,30.99 ; M4.GND12 3.52,32.07 ; 31.08,17.82 M4.GND6 ; M4.GND6 32.1,18.83 ; M4.GND6 32.1,16.8 ; M4.GND6 33.12,17.82 ; 2.93,59.23 P13.8 ; P13.8 4.01,60.31 ; P13.8 4.01,58.15 ; P13.8 5.09,59.23 ; M4.GND8 28.42,17.82 ; M4.GND8 26.38,17.82 ; M4.GND8 27.4,16.8 ; M4.GND8 27.4,18.83 ; 37.1,31.05 M4.GND18 ; M4.GND18 36.08,32.07 ; M4.GND18 37.1,33.08 ; M4.GND18 38.12,32.07 ; 134.57,108.56 J3.3 ; J3.3 135.84,109.83 ; J3.3 135.84,107.29 ; J3.3 137.11,108.56 ; 23.52,20.99 M4.GND20 ; M4.GND20 24.6,22.07 ; M4.GND20 25.68,20.99 ; M4.GND20 24.6,19.91 ; 38.52,17.82 M4.GND4 ; M4.GND4 40.68,17.82 ; M4.GND4 39.6,16.74 ; M4.GND4 39.6,18.9 ; 145.15,32.31 P2.GND1 ; P2.GND1 143.88,33.58 ; P2.GND1 145.15,34.85 ; P2.GND1 146.42,33.58 ; 58.42,107.29 J2.2 ; J2.2 58.42,109.83 ; J2.2 59.69,108.56 ; J2.2 57.15,108.56 ; 145.15,85.15 P1.GND3 ; P1.GND3 143.88,86.42 ; P1.GND3 146.42,86.42 ; P1.GND3 145.15,87.69 ; P13.4 4.01,55.23 ; P13.4 2.93,54.15 ; P13.4 4.01,53.07 ; P13.4 5.09,54.15 ; 40.68,29.74 M4.GND1 ; M4.GND1 42.72,29.74 ; M4.GND1 41.7,30.75 ; M4.GND1 41.7,28.72 ; P1.GND4 138.75,87.69 ; P1.GND4 138.75,85.15 ; P1.GND4 140.02,86.42 ; P1.GND4 137.48,86.42 ; 130.76,107.29 J3.2 ; J3.2 130.76,109.83 ; J3.2 132.03,108.56 ; J3.2 129.49,108.56 ; 23.52,26.39 M4.GND19 ; M4.GND19 24.6,25.31 ; M4.GND19 24.6,27.47 ; M4.GND19 25.68,26.39 ; 83.82,107.29 J1.3 ; J1.3 83.82,109.83 ; J1.3 82.55,108.56 ; J1.3 85.09,108.56 ; 115.52,102.21 J4.5 ; J4.5 115.52,104.75 ; J4.5 116.79,103.48 ; J4.5 114.25,103.48 ; M4.GND17 35.55,32.07 ; M4.GND17 34.6,33.02 ; M4.GND17 33.65,32.07 ; 77.47,103.48 J1.5 ; J1.5 78.74,104.75 ; J1.5 80.01,103.48 ; J1.5 78.74,102.21 ; 138.75,32.31 P2.GND2 ; P2.GND2 140.02,33.58 ; P2.GND2 137.48,33.58 ; P2.GND2 138.75,34.85 ; P1.GND2 138.75,78.99 ; P1.GND2 138.75,76.45 ; P1.GND2 137.48,77.72 ; P1.GND2 140.02,77.72 ; 143.88,77.72 P1.GND1 ; P1.GND1 145.15,78.99 ; P1.GND1 145.15,76.45 ; P1.GND1 146.42,77.72 ; J2.5 59.69,103.48 ; J2.5 57.15,103.48 ; J2.5 58.42,104.75 ; J2.5 58.42,102.21 ; 78.74,107.29 J1.2 ; J1.2 78.74,109.83 ; J1.2 77.47,108.56 ; J1.2 80.01,108.56 ; 26.38,32.07 M4.GND15 ; M4.GND15 27.4,33.08 ; M4.GND15 27.4,31.05 ; M4.GND15 28.42,32.07 ; M4.GND7 29.6,18.9 ; M4.GND7 28.52,17.82 ; M4.GND7 30.68,17.82 ; M4.GND7 29.6,16.74 ; 114.25,108.56 J4.2 ; J4.2 115.52,107.29 ; J4.2 115.52,109.83 ; J4.2 116.79,108.56 ; 119.33,108.56 J4.3 ; J4.3 120.6,109.83 ; J4.3 121.87,108.56 ; J4.3 120.6,107.29 ; 41.7,19.12 M4.GND3 ; M4.GND3 40.68,20.14 ; M4.GND3 42.72,20.14 ; M4.GND3 41.7,21.15 ; 48.43,54.18 P6.1 ; P6.1 49.5,53.1 ; P6.1 50.58,54.18 ; P6.1 49.5,55.26 ; 40.68,24.94 M4.GND2 ; M4.GND2 42.72,24.94 ; M4.GND2 41.7,23.92 ; M4.GND2 41.7,25.95 ; 5.47,51.61 P13.1 ; P13.1 6.55,50.53 ; P13.1 6.55,52.69 ; P13.1 7.63,51.61 ; J2.4 63.5,104.75 ; J2.4 64.77,103.48 ; J2.4 63.5,102.21 ; J2.4 62.23,103.48
  L4_GND w0.203: 73.64,17.44 73.76,17.56 v5(73.76,18.08) 73.76,18.6 73.72,18.64
  L4_GND w0.508: 8.52,17.82 M4.GND10 ; M4.GND10 10.68,17.82 ; M4.GND10 9.6,16.74 ; M4.GND10 9.6,18.9 ; 40.68,20.14 M4.GND3 ; M4.GND3 42.72,20.14 ; M4.GND3 41.7,21.15 ; M4.GND3 41.7,19.12 ; M4.GND2 42.72,24.94 ; M4.GND2 40.68,24.94 ; M4.GND2 41.7,25.95 ; M4.GND2 41.7,23.92 ; M4.GND19 24.6,27.47 ; M4.GND19 23.52,26.39 ; M4.GND19 24.6,25.31 ; M4.GND19 25.68,26.39 ; 134.57,108.56 J3.3 ; J3.3 135.84,109.83 ; J3.3 135.84,107.29 ; J3.3 137.11,108.56 ; M4.GND7 30.68,17.82 ; M4.GND7 28.52,17.82 ; M4.GND7 29.6,16.74 ; M4.GND7 29.6,18.9 ; M4.GND12 5.68,32.07 ; M4.GND12 3.52,32.07 ; M4.GND12 4.6,33.15 ; M4.GND12 4.6,30.99 ; 78.74,107.29 J1.2 ; J1.2 77.47,108.56 ; J1.2 80.01,108.56 ; J1.2 78.74,109.83 ; J2.3 64.77,108.56 ; J2.3 63.5,107.29 ; J2.3 62.23,108.56 ; J2.3 63.5,109.83 ; 57.15,108.56 J2.2 ; J2.2 59.69,108.56 ; J2.2 58.42,109.83 ; J2.2 58.42,107.29 ; J1.5 78.74,104.75 ; J1.5 80.01,103.48 ; J1.5 77.47,103.48 ; J1.5 78.74,102.21 ; 5.61,97.17 P8.1 ; P8.1 4.41,98.37 ; P8.1 5.61,99.58 ; P8.1 6.82,98.37 ; M4.GND13 15.68,32.07 ; M4.GND13 14.6,30.99 ; M4.GND13 14.6,33.15 ; M4.GND13 13.52,32.07 ; P2.GND2 140.02,33.58 ; P2.GND2 138.75,34.85 ; P2.GND2 137.48,33.58 ; P2.GND2 138.75,32.31 ; 45.47,105.28 S12.3 ; S12.3 45.47,108.08 ; S12.3 44.07,106.68 ; S12.3 46.86,106.68 ; J4.5 116.79,103.48 ; J4.5 114.25,103.48 ; J4.5 115.52,102.21 ; J4.5 115.52,104.75 ; 63.5,102.21 J2.4 ; J2.4 64.77,103.48 ; J2.4 62.23,103.48 ; J2.4 63.5,104.75 ; P1.GND1 146.42,77.72 ; P1.GND1 145.15,76.45 ; P1.GND1 145.15,78.99 ; P1.GND1 143.88,77.72 ; 137.48,77.72 P1.GND2 ; P1.GND2 140.02,77.72 ; P1.GND2 138.75,76.45 ; P1.GND2 138.75,78.99 ; 31.08,32.07 M4.GND16 ; M4.GND16 32.1,31.05 ; M4.GND16 33.12,32.07 ; M4.GND16 32.1,33.08 ; J3.4 137.11,103.48 ; J3.4 135.84,102.21 ; J3.4 135.84,104.75 ; J3.4 134.57,103.48 ; 143.88,86.42 P1.GND3 ; P1.GND3 145.15,85.15 ; P1.GND3 146.42,86.42 ; P1.GND3 145.15,87.69 ; P13.1 7.63,51.61 ; P13.1 6.55,50.53 ; P13.1 6.55,52.69 ; P13.1 5.47,51.61 ; M4.GND11 5.68,23.49 ; M4.GND11 3.52,23.49 ; M4.GND11 4.6,22.41 ; M4.GND11 4.6,24.57 ; J4.2 116.79,108.56 ; J4.2 114.25,108.56 ; J4.2 115.52,109.83 ; J4.2 115.52,107.29 ; 33.65,32.07 M4.GND17 ; M4.GND17 35.55,32.07 ; M4.GND17 34.6,33.02 ; J3.2 130.76,109.83 ; J3.2 130.76,107.29 ; J3.2 132.03,108.56 ; J3.2 129.49,108.56 ; 4.01,55.61 P13.6 ; P13.6 2.93,56.69 ; P13.6 5.09,56.69 ; P13.6 4.01,57.77 ; 23.52,20.99 M4.GND20 ; M4.GND20 25.68,20.99 ; M4.GND20 24.6,19.91 ; M4.GND20 24.6,22.07 ; 137.48,42.28 P2.GND4 ; P2.GND4 138.75,41.01 ; P2.GND4 138.75,43.55 ; P2.GND4 140.02,42.28 ; J1.4 83.82,104.75 ; J1.4 83.82,102.21 ; J1.4 82.55,103.48 ; J1.4 85.09,103.48 ; M4.GND14 25.68,32.07 ; M4.GND14 24.6,30.99 ; M4.GND14 24.6,33.15 ; M4.GND14 23.52,32.07 ; 39.6,16.74 M4.GND4 ; M4.GND4 39.6,18.9 ; M4.GND4 38.52,17.82 ; M4.GND4 40.68,17.82 ; 18.52,17.82 M4.GND9 ; M4.GND9 19.6,16.74 ; M4.GND9 19.6,18.9 ; M4.GND9 20.68,17.82 ; 143.88,33.58 P2.GND1 ; P2.GND1 145.15,34.85 ; P2.GND1 145.15,32.31 ; P2.GND1 146.42,33.58 ; 48.43,54.18 P6.1 ; P6.1 49.5,53.1 ; P6.1 50.58,54.18 ; P6.1 49.5,55.26 ; M4.GND18 38.12,32.07 ; M4.GND18 37.1,33.08 ; M4.GND18 37.1,31.05 ; M4.GND18 36.08,32.07 ; 27.4,16.8 M4.GND8 ; M4.GND8 27.4,18.83 ; M4.GND8 26.38,17.82 ; M4.GND8 28.42,17.82 ; 40.68,29.74 M4.GND1 ; M4.GND1 42.72,29.74 ; M4.GND1 41.7,30.75 ; M4.GND1 41.7,28.72 ; 26.38,32.07 M4.GND15 ; M4.GND15 27.4,33.08 ; M4.GND15 28.42,32.07 ; M4.GND15 27.4,31.05 ; J3.5 130.76,104.75 ; J3.5 129.49,103.48 ; J3.5 132.03,103.48 ; J3.5 130.76,102.21 ; P1.GND4 138.75,87.69 ; P1.GND4 137.48,86.42 ; P1.GND4 140.02,86.42 ; P1.GND4 138.75,85.15 ; J4.3 120.6,109.83 ; J4.3 120.6,107.29 ; J4.3 121.87,108.56 ; J4.3 119.33,108.56 ; M4.GND5 37.1,18.83 ; M4.GND5 38.12,17.82 ; M4.GND5 37.1,16.8 ; M4.GND5 36.08,17.82 ; P13.8 4.01,60.31 ; P13.8 4.01,58.15 ; P13.8 5.09,59.23 ; P13.8 2.93,59.23 ; 119.33,103.48 J4.4 ; J4.4 120.6,102.21 ; J4.4 120.6,104.75 ; J4.4 121.87,103.48 ; J2.5 58.42,104.75 ; J2.5 57.15,103.48 ; J2.5 59.69,103.48 ; J2.5 58.42,102.21 ; P13.4 4.01,55.23 ; P13.4 5.09,54.15 ; P13.4 2.93,54.15 ; P13.4 4.01,53.07 ; M4.GND6 32.1,18.83 ; M4.GND6 31.08,17.82 ; M4.GND6 32.1,16.8 ; M4.GND6 33.12,17.82 ; 143.88,42.28 P2.GND3 ; P2.GND3 145.15,43.55 ; P2.GND3 145.15,41.01 ; P2.GND3 146.42,42.28 ; 82.55,108.56 J1.3 ; J1.3 83.82,107.29 ; J1.3 83.82,109.83 ; J1.3 85.09,108.56 ; 4.01,50.53 P13.2 ; P13.2 4.01,52.69 ; P13.2 5.09,51.61 ; P13.2 2.93,51.61
  L5_PWR w0.508: J2.2 58.42,109.83 ; J2.2 57.15,108.56 ; J2.2 59.69,108.56 ; S12.3 46.86,106.68 ; S12.3 45.47,105.28 ; S12.3 44.07,106.68 ; S12.3 45.47,108.08
  L6_PWR w0.508: 32.1,16.8 M4.GND6 ; M4.GND6 33.12,17.82 ; M4.GND6 32.1,18.83 ; M4.GND6 31.08,17.82 ; 23.52,32.07 M4.GND14 ; M4.GND14 24.6,33.15 ; M4.GND14 25.68,32.07 ; M4.GND14 24.6,30.99 ; M4.GND9 19.6,18.9 ; M4.GND9 18.52,17.82 ; M4.GND9 20.68,17.82 ; M4.GND9 19.6,16.74 ; 36.08,32.07 M4.GND18 ; M4.GND18 37.1,33.08 ; M4.GND18 37.1,31.05 ; M4.GND7 29.6,18.9 ; M4.GND7 30.68,17.82 ; M4.GND7 28.52,17.82 ; M4.GND7 29.6,16.74 ; 23.52,20.99 M4.GND20 ; M4.GND20 24.6,22.07 ; M4.GND20 25.68,20.99 ; M4.GND20 24.6,19.91 ; M4.GND16 33.12,32.07 ; M4.GND16 32.1,31.05 ; M4.GND16 32.1,33.08 ; M4.GND16 31.08,32.07 ; 27.4,31.05 M4.GND15 ; M4.GND15 28.42,32.07 ; M4.GND15 26.38,32.07 ; M4.GND15 27.4,33.08 ; M4.GND5 37.1,18.83 ; M4.GND5 36.08,17.82 ; M4.GND5 37.1,16.8 ; 3.52,32.07 M4.GND12 ; M4.GND12 4.6,33.15 ; M4.GND12 5.68,32.07 ; M4.GND12 4.6,30.99 ; M4.GND17 34.6,33.02 ; M4.GND17 33.65,32.07 ; M4.GND17 35.55,32.07 ; 24.6,25.31 M4.GND19 ; M4.GND19 25.68,26.39 ; M4.GND19 23.52,26.39 ; M4.GND19 24.6,27.47 ; 14.6,30.99 M4.GND13 ; M4.GND13 14.6,33.15 ; M4.GND13 13.52,32.07 ; M4.GND13 15.68,32.07 ; M4.GND8 28.42,17.82 ; M4.GND8 27.4,16.8 ; M4.GND8 26.38,17.82 ; M4.GND8 27.4,18.83 ; 4.6,22.41 M4.GND11 ; M4.GND11 3.52,23.49 ; M4.GND11 5.68,23.49 ; M4.GND11 4.6,24.57 ; 8.52,17.82 M4.GND10 ; M4.GND10 9.6,18.9 ; M4.GND10 10.68,17.82 ; M4.GND10 9.6,16.74
  L7_GND w0.203: 73.8,18.69 73.76,18.65 v5(73.76,18.08) 73.76,17.55 73.71,17.5
  L7_GND w0.508: 4.01,50.53 P13.2 ; P13.2 5.09,51.61 ; P13.2 4.01,52.69 ; P13.2 2.93,51.61 ; P1.GND3 146.42,86.42 ; P1.GND3 145.15,85.15 ; P1.GND3 143.88,86.42 ; P1.GND3 145.15,87.69 ; S12.3 45.47,108.08 ; S12.3 45.47,105.28 ; S12.3 44.07,106.68 ; S12.3 46.86,106.68 ; 135.84,102.21 J3.4 ; J3.4 135.84,104.75 ; J3.4 134.57,103.48 ; J3.4 137.11,103.48 ; J2.5 59.69,103.48 ; J2.5 58.42,102.21 ; J2.5 58.42,104.75 ; J2.5 57.15,103.48 ; 138.75,41.01 P2.GND4 ; P2.GND4 137.48,42.28 ; P2.GND4 140.02,42.28 ; P2.GND4 138.75,43.55 ; M4.GND15 28.42,32.07 ; M4.GND15 27.4,33.08 ; M4.GND15 27.4,31.05 ; M4.GND15 26.38,32.07 ; M4.GND18 38.12,32.07 ; M4.GND18 37.1,33.08 ; M4.GND18 36.08,32.07 ; M4.GND18 37.1,31.05 ; P13.4 5.09,54.15 ; P13.4 4.01,55.23 ; P13.4 2.93,54.15 ; P13.4 4.01,53.07 ; 57.15,108.56 J2.2 ; J2.2 59.69,108.56 ; J2.2 58.42,109.83 ; J2.2 58.42,107.29 ; 40.68,20.14 M4.GND3 ; M4.GND3 42.72,20.14 ; M4.GND3 41.7,19.12 ; M4.GND3 41.7,21.15 ; 36.08,17.82 M4.GND5 ; M4.GND5 37.1,18.83 ; M4.GND5 37.1,16.8 ; M4.GND5 38.12,17.82 ; 138.75,32.31 P2.GND2 ; P2.GND2 137.48,33.58 ; P2.GND2 138.75,34.85 ; P2.GND2 140.02,33.58 ; 138.75,85.15 P1.GND4 ; P1.GND4 140.02,86.42 ; P1.GND4 138.75,87.69 ; P1.GND4 137.48,86.42 ; 14.6,30.99 M4.GND13 ; M4.GND13 14.6,33.15 ; M4.GND13 13.52,32.07 ; M4.GND13 15.68,32.07 ; 62.23,103.48 J2.4 ; J2.4 63.5,104.75 ; J2.4 64.77,103.48 ; J2.4 63.5,102.21 ; M4.GND10 9.6,18.9 ; M4.GND10 10.68,17.82 ; M4.GND10 9.6,16.74 ; M4.GND10 8.52,17.82 ; 120.6,107.29 J4.3 ; J4.3 121.87,108.56 ; J4.3 120.6,109.83 ; J4.3 119.33,108.56 ; J4.4 121.87,103.48 ; J4.4 120.6,102.21 ; J4.4 119.33,103.48 ; J4.4 120.6,104.75 ; M4.GND20 25.68,20.99 ; M4.GND20 24.6,19.91 ; M4.GND20 23.52,20.99 ; M4.GND20 24.6,22.07 ; 138.75,76.45 P1.GND2 ; P1.GND2 140.02,77.72 ; P1.GND2 137.48,77.72 ; P1.GND2 138.75,78.99 ; M4.GND8 27.4,18.83 ; M4.GND8 27.4,16.8 ; M4.GND8 28.42,17.82 ; M4.GND8 26.38,17.82 ; P1.GND1 146.42,77.72 ; P1.GND1 145.15,76.45 ; P1.GND1 145.15,78.99 ; P1.GND1 143.88,77.72 ; J1.3 83.82,109.83 ; J1.3 82.55,108.56 ; J1.3 83.82,107.29 ; J1.3 85.09,108.56 ; M4.GND12 5.68,32.07 ; M4.GND12 4.6,30.99 ; M4.GND12 4.6,33.15 ; M4.GND12 3.52,32.07 ; 24.6,25.31 M4.GND19 ; M4.GND19 23.52,26.39 ; M4.GND19 24.6,27.47 ; M4.GND19 25.68,26.39 ; J1.2 78.74,109.83 ; J1.2 80.01,108.56 ; J1.2 77.47,108.56 ; J1.2 78.74,107.29 ; J3.2 130.76,109.83 ; J3.2 132.03,108.56 ; J3.2 130.76,107.29 ; J3.2 129.49,108.56 ; 130.76,102.21 J3.5 ; J3.5 132.03,103.48 ; J3.5 129.49,103.48 ; J3.5 130.76,104.75 ; J1.4 83.82,104.75 ; J1.4 82.55,103.48 ; J1.4 85.09,103.48 ; J1.4 83.82,102.21 ; 4.41,98.37 P8.1 ; P8.1 5.61,97.17 ; P8.1 5.61,99.58 ; P8.1 6.82,98.37 ; 32.1,31.05 M4.GND16 ; M4.GND16 32.1,33.08 ; M4.GND16 33.12,32.07 ; M4.GND16 31.08,32.07 ; P2.GND3 146.42,42.28 ; P2.GND3 143.88,42.28 ; P2.GND3 145.15,41.01 ; P2.GND3 145.15,43.55 ; 40.68,24.94 M4.GND2 ; M4.GND2 41.7,23.92 ; M4.GND2 42.72,24.94 ; M4.GND2 41.7,25.95 ; M4.GND17 34.6,33.02 ; M4.GND17 35.55,32.07 ; M4.GND17 33.65,32.07 ; 24.6,30.99 M4.GND14 ; M4.GND14 23.52,32.07 ; M4.GND14 25.68,32.07 ; M4.GND14 24.6,33.15 ; J4.2 116.79,108.56 ; J4.2 114.25,108.56 ; J4.2 115.52,107.29 ; J4.2 115.52,109.83 ; P13.1 7.63,51.61 ; P13.1 6.55,50.53 ; P13.1 5.47,51.61 ; P13.1 6.55,52.69 ; P13.8 5.09,59.23 ; P13.8 4.01,58.15 ; P13.8 4.01,60.31 ; P13.8 2.93,59.23 ; M4.GND7 29.6,18.9 ; M4.GND7 30.68,17.82 ; M4.GND7 29.6,16.74 ; M4.GND7 28.52,17.82 ; M4.GND4 39.6,18.9 ; M4.GND4 40.68,17.82 ; M4.GND4 38.52,17.82 ; M4.GND4 39.6,16.74 ; 143.88,33.58 P2.GND1 ; P2.GND1 145.15,34.85 ; P2.GND1 146.42,33.58 ; P2.GND1 145.15,32.31 ; J3.3 137.11,108.56 ; J3.3 134.57,108.56 ; J3.3 135.84,109.83 ; J3.3 135.84,107.29 ; 48.43,54.18 P6.1 ; P6.1 49.5,53.1 ; P6.1 50.58,54.18 ; P6.1 49.5,55.26 ; 4.6,22.41 M4.GND11 ; M4.GND11 4.6,24.57 ; M4.GND11 3.52,23.49 ; M4.GND11 5.68,23.49 ; 114.25,103.48 J4.5 ; J4.5 115.52,102.21 ; J4.5 116.79,103.48 ; J4.5 115.52,104.75 ; 4.01,55.61 P13.6 ; P13.6 2.93,56.69 ; P13.6 5.09,56.69 ; P13.6 4.01,57.77 ; 32.1,16.8 M4.GND6 ; M4.GND6 32.1,18.83 ; M4.GND6 31.08,17.82 ; M4.GND6 33.12,17.82 ; 63.5,107.29 J2.3 ; J2.3 62.23,108.56 ; J2.3 64.77,108.56 ; J2.3 63.5,109.83 ; 77.47,103.48 J1.5 ; J1.5 80.01,103.48 ; J1.5 78.74,102.21 ; J1.5 78.74,104.75 ; M4.GND1 41.7,30.75 ; M4.GND1 42.72,29.74 ; M4.GND1 40.68,29.74 ; M4.GND1 41.7,28.72 ; 18.52,17.82 M4.GND9 ; M4.GND9 19.6,16.74 ; M4.GND9 20.68,17.82 ; M4.GND9 19.6,18.9
  L8_SIG w0.203: v5(73.76,18.08) 73.76,17.41
  L8_SIG w0.508: P13.2 4.01,52.69 ; P13.2 5.09,51.61 ; P13.2 2.93,51.61 ; P13.2 4.01,50.53 ; M4.GND13 14.6,33.15 ; M4.GND13 14.6,30.99 ; M4.GND13 13.52,32.07 ; M4.GND13 15.68,32.07 ; 24.6,25.31 M4.GND19 ; M4.GND19 23.52,26.39 ; M4.GND19 24.6,27.47 ; M4.GND19 25.68,26.39 ; 135.84,107.29 J3.3 ; J3.3 134.57,108.56 ; J3.3 135.84,109.83 ; J3.3 137.11,108.56 ; P2.GND4 140.02,42.28 ; P2.GND4 138.75,41.01 ; P2.GND4 138.75,43.55 ; 120.6,107.29 J4.3 ; J4.3 119.33,108.56 ; J4.3 120.6,109.83 ; J4.3 121.87,108.56 ; 137.48,77.72 P1.GND2 ; P1.GND2 138.75,76.45 ; P1.GND2 138.75,78.99 ; P1.GND2 140.02,77.72 ; M4.GND10 9.6,18.9 ; M4.GND10 8.52,17.82 ; M4.GND10 9.6,16.74 ; M4.GND10 10.68,17.82 ; 58.42,102.21 J2.5 ; J2.5 57.15,103.48 ; J2.5 58.42,104.75 ; J2.5 59.69,103.48 ; J4.5 115.52,104.75 ; J4.5 115.52,102.21 ; J4.5 114.25,103.48 ; J4.5 116.79,103.48 ; M4.GND17 35.55,32.07 ; M4.GND17 33.65,32.07 ; M4.GND17 34.6,33.02 ; 18.52,17.82 M4.GND9 ; M4.GND9 19.6,16.74 ; M4.GND9 19.6,18.9 ; M4.GND9 20.68,17.82 ; M4.GND2 42.72,24.94 ; M4.GND2 41.7,23.92 ; M4.GND2 40.68,24.94 ; M4.GND2 41.7,25.95 ; P1.GND4 140.02,86.42 ; P1.GND4 138.75,87.69 ; P1.GND4 138.75,85.15 ; P1.GND4 137.48,86.42 ; M4.GND11 5.68,23.49 ; M4.GND11 4.6,22.41 ; M4.GND11 3.52,23.49 ; M4.GND11 4.6,24.57 ; P2.GND1 146.42,33.58 ; P2.GND1 145.15,32.31 ; P2.GND1 145.15,34.85 ; P2.GND1 143.88,33.58 ; M4.GND8 27.4,18.83 ; M4.GND8 26.38,17.82 ; M4.GND8 27.4,16.8 ; M4.GND8 28.42,17.82 ; P6.1 50.58,54.18 ; P6.1 49.5,55.26 ; P6.1 49.5,53.1 ; P6.1 48.43,54.18 ; 129.49,103.48 J3.5 ; J3.5 130.76,104.75 ; J3.5 132.03,103.48 ; J3.5 130.76,102.21 ; M4.GND5 37.1,18.83 ; M4.GND5 38.12,17.82 ; M4.GND5 37.1,16.8 ; M4.GND5 36.08,17.82 ; 26.38,32.07 M4.GND15 ; M4.GND15 28.42,32.07 ; M4.GND15 27.4,31.05 ; M4.GND15 27.4,33.08 ; J3.4 135.84,104.75 ; J3.4 135.84,102.21 ; J3.4 134.57,103.48 ; J3.4 137.11,103.48 ; 78.74,107.29 J1.2 ; J1.2 80.01,108.56 ; J1.2 77.47,108.56 ; J1.2 78.74,109.83 ; 58.42,107.29 J2.2 ; J2.2 58.42,109.83 ; J2.2 57.15,108.56 ; J2.2 59.69,108.56 ; P1.GND1 146.42,77.72 ; P1.GND1 143.88,77.72 ; P1.GND1 145.15,78.99 ; P1.GND1 145.15,76.45 ; P13.1 6.55,52.69 ; P13.1 5.47,51.61 ; P13.1 6.55,50.53 ; P13.1 7.63,51.61 ; 2.93,56.69 P13.6 ; P13.6 4.01,57.77 ; P13.6 4.01,55.61 ; P13.6 5.09,56.69 ; 37.1,31.05 M4.GND18 ; M4.GND18 38.12,32.07 ; M4.GND18 37.1,33.08 ; M4.GND18 36.08,32.07 ; 119.33,103.48 J4.4 ; J4.4 120.6,102.21 ; J4.4 121.87,103.48 ; J4.4 120.6,104.75 ; 62.23,108.56 J2.3 ; J2.3 64.77,108.56 ; J2.3 63.5,109.83 ; J2.3 63.5,107.29 ; 31.08,32.07 M4.GND16 ; M4.GND16 33.12,32.07 ; M4.GND16 32.1,33.08 ; M4.GND16 32.1,31.05 ; S12.3 46.86,106.68 ; S12.3 45.47,108.08 ; S12.3 45.47,105.28 ; S12.3 44.07,106.68 ; M4.GND1 41.7,30.75 ; M4.GND1 42.72,29.74 ; M4.GND1 41.7,28.72 ; M4.GND1 40.68,29.74 ; 4.01,58.15 P13.8 ; P13.8 5.09,59.23 ; P13.8 2.93,59.23 ; P13.8 4.01,60.31 ; 130.76,107.29 J3.2 ; J3.2 129.49,108.56 ; J3.2 132.03,108.56 ; J3.2 130.76,109.83 ; 2.93,54.15 P13.4 ; P13.4 4.01,53.07 ; P13.4 4.01,55.23 ; P13.4 5.09,54.15 ; P1.GND3 146.42,86.42 ; P1.GND3 145.15,85.15 ; P1.GND3 143.88,86.42 ; P1.GND3 145.15,87.69 ; M4.GND14 24.6,33.15 ; M4.GND14 25.68,32.07 ; M4.GND14 23.52,32.07 ; M4.GND14 24.6,30.99 ; P2.GND2 140.02,33.58 ; P2.GND2 138.75,32.31 ; P2.GND2 138.75,34.85 ; P2.GND3 146.42,42.28 ; P2.GND3 143.88,42.28 ; P2.GND3 145.15,41.01 ; P2.GND3 145.15,43.55 ; M4.GND3 41.7,21.15 ; M4.GND3 41.7,19.12 ; M4.GND3 40.68,20.14 ; M4.GND3 42.72,20.14 ; 28.52,17.82 M4.GND7 ; M4.GND7 29.6,18.9 ; M4.GND7 30.68,17.82 ; M4.GND7 29.6,16.74 ; J4.2 116.79,108.56 ; J4.2 114.25,108.56 ; J4.2 115.52,107.29 ; J4.2 115.52,109.83 ; J1.5 80.01,103.48 ; J1.5 78.74,102.21 ; J1.5 78.74,104.75 ; J1.5 77.47,103.48 ; 32.1,16.8 M4.GND6 ; M4.GND6 32.1,18.83 ; M4.GND6 31.08,17.82 ; M4.GND6 33.12,17.82 ; M4.GND20 25.68,20.99 ; M4.GND20 24.6,19.91 ; M4.GND20 23.52,20.99 ; M4.GND20 24.6,22.07 ; 83.82,107.29 J1.3 ; J1.3 83.82,109.83 ; J1.3 85.09,108.56 ; J1.3 82.55,108.56 ; 63.5,102.21 J2.4 ; J2.4 64.77,103.48 ; J2.4 63.5,104.75 ; J2.4 62.23,103.48 ; M4.GND4 39.6,18.9 ; M4.GND4 39.6,16.74 ; M4.GND4 38.52,17.82 ; M4.GND4 40.68,17.82 ; 3.52,32.07 M4.GND12 ; M4.GND12 5.68,32.07 ; M4.GND12 4.6,30.99 ; M4.GND12 4.6,33.15 ; 5.61,97.17 P8.1 ; P8.1 4.41,98.37 ; P8.1 5.61,99.58 ; P8.1 6.82,98.37 ; 82.55,103.48 J1.4 ; J1.4 83.82,104.75 ; J1.4 85.09,103.48 ; J1.4 83.82,102.21
  L9_GND w0.203: 73.76,17.45 73.76,17.45 v5(73.76,18.08) 73.76,18.79 73.77,18.8
  L9_GND w0.508: 63.5,107.29 J2.3 ; J2.3 64.77,108.56 ; J2.3 62.23,108.56 ; J2.3 63.5,109.83 ; 57.15,108.56 J2.2 ; J2.2 59.69,108.56 ; J2.2 58.42,109.83 ; J2.2 58.42,107.29 ; P13.6 5.09,56.69 ; P13.6 4.01,55.61 ; P13.6 4.01,57.77 ; P13.6 2.93,56.69 ; P1.GND3 145.15,87.69 ; P1.GND3 146.42,86.42 ; P1.GND3 145.15,85.15 ; P1.GND3 143.88,86.42 ; J3.2 130.76,109.83 ; J3.2 129.49,108.56 ; J3.2 132.03,108.56 ; J3.2 130.76,107.29 ; 115.52,107.29 J4.2 ; J4.2 115.52,109.83 ; J4.2 114.25,108.56 ; J4.2 116.79,108.56 ; J2.4 64.77,103.48 ; J2.4 63.5,104.75 ; J2.4 62.23,103.48 ; J2.4 63.5,102.21 ; 135.84,107.29 J3.3 ; J3.3 134.57,108.56 ; J3.3 137.11,108.56 ; J3.3 135.84,109.83 ; 143.88,77.72 P1.GND1 ; P1.GND1 145.15,76.45 ; P1.GND1 145.15,78.99 ; P1.GND1 146.42,77.72 ; 32.1,31.05 M4.GND16 ; M4.GND16 33.12,32.07 ; M4.GND16 32.1,33.08 ; M4.GND16 31.08,32.07 ; M4.GND3 41.7,21.15 ; M4.GND3 40.68,20.14 ; M4.GND3 41.7,19.12 ; M4.GND3 42.72,20.14 ; 120.6,107.29 J4.3 ; J4.3 120.6,109.83 ; J4.3 121.87,108.56 ; J4.3 119.33,108.56 ; M4.GND4 39.6,18.9 ; M4.GND4 40.68,17.82 ; M4.GND4 39.6,16.74 ; M4.GND4 38.52,17.82 ; 28.52,17.82 M4.GND7 ; M4.GND7 29.6,16.74 ; M4.GND7 29.6,18.9 ; M4.GND7 30.68,17.82 ; M4.GND12 4.6,33.15 ; M4.GND12 4.6,30.99 ; M4.GND12 5.68,32.07 ; M4.GND12 3.52,32.07 ; P2.GND4 140.02,42.28 ; P2.GND4 138.75,43.55 ; P2.GND4 137.48,42.28 ; P2.GND4 138.75,41.01 ; 137.48,86.42 P1.GND4 ; P1.GND4 140.02,86.42 ; P1.GND4 138.75,87.69 ; P1.GND4 138.75,85.15 ; 82.55,108.56 J1.3 ; J1.3 83.82,107.29 ; J1.3 83.82,109.83 ; J1.3 85.09,108.56 ; 77.47,103.48 J1.5 ; J1.5 78.74,104.75 ; J1.5 80.01,103.48 ; J1.5 78.74,102.21 ; 48.43,54.18 P6.1 ; P6.1 49.5,53.1 ; P6.1 50.58,54.18 ; P6.1 49.5,55.26 ; 82.55,103.48 J1.4 ; J1.4 83.82,104.75 ; J1.4 85.09,103.48 ; J1.4 83.82,102.21 ; 23.52,26.39 M4.GND19 ; M4.GND19 25.68,26.39 ; M4.GND19 24.6,27.47 ; M4.GND19 24.6,25.31 ; 130.76,102.21 J3.5 ; J3.5 129.49,103.48 ; J3.5 130.76,104.75 ; J3.5 132.03,103.48 ; 78.74,107.29 J1.2 ; J1.2 78.74,109.83 ; J1.2 77.47,108.56 ; J1.2 80.01,108.56 ; 40.68,29.74 M4.GND1 ; M4.GND1 42.72,29.74 ; M4.GND1 41.7,30.75 ; M4.GND1 41.7,28.72 ; M4.GND20 25.68,20.99 ; M4.GND20 24.6,19.91 ; M4.GND20 24.6,22.07 ; M4.GND20 23.52,20.99 ; 24.6,30.99 M4.GND14 ; M4.GND14 25.68,32.07 ; M4.GND14 23.52,32.07 ; M4.GND14 24.6,33.15 ; P2.GND2 140.02,33.58 ; P2.GND2 138.75,34.85 ; P2.GND2 137.48,33.58 ; P2.GND2 138.75,32.31 ; M4.GND5 37.1,18.83 ; M4.GND5 37.1,16.8 ; M4.GND5 36.08,17.82 ; M4.GND5 38.12,17.82 ; 4.01,53.07 P13.4 ; P13.4 4.01,55.23 ; P13.4 5.09,54.15 ; P13.4 2.93,54.15 ; M4.GND18 38.12,32.07 ; M4.GND18 37.1,33.08 ; M4.GND18 37.1,31.05 ; M4.GND18 36.08,32.07 ; 143.88,42.28 P2.GND3 ; P2.GND3 146.42,42.28 ; P2.GND3 145.15,41.01 ; P2.GND3 145.15,43.55 ; M4.GND6 32.1,18.83 ; M4.GND6 32.1,16.8 ; M4.GND6 31.08,17.82 ; M4.GND6 33.12,17.82 ; P13.1 7.63,51.61 ; P13.1 5.47,51.61 ; P13.1 6.55,52.69 ; P13.1 6.55,50.53 ; M4.GND8 28.42,17.82 ; M4.GND8 27.4,16.8 ; M4.GND8 27.4,18.83 ; M4.GND8 26.38,17.82 ; M4.GND10 10.68,17.82 ; M4.GND10 9.6,16.74 ; M4.GND10 8.52,17.82 ; M4.GND10 9.6,18.9 ; 115.52,102.21 J4.5 ; J4.5 114.25,103.48 ; J4.5 116.79,103.48 ; J4.5 115.52,104.75 ; J3.4 135.84,104.75 ; J3.4 135.84,102.21 ; J3.4 134.57,103.48 ; J3.4 137.11,103.48 ; M4.GND2 42.72,24.94 ; M4.GND2 40.68,24.94 ; M4.GND2 41.7,25.95 ; M4.GND2 41.7,23.92 ; 3.52,23.49 M4.GND11 ; M4.GND11 4.6,22.41 ; M4.GND11 4.6,24.57 ; M4.GND11 5.68,23.49 ; 120.6,102.21 J4.4 ; J4.4 121.87,103.48 ; J4.4 120.6,104.75 ; J4.4 119.33,103.48 ; 143.88,33.58 P2.GND1 ; P2.GND1 146.42,33.58 ; P2.GND1 145.15,32.31 ; P2.GND1 145.15,34.85 ; M4.GND13 15.68,32.07 ; M4.GND13 13.52,32.07 ; M4.GND13 14.6,33.15 ; M4.GND13 14.6,30.99 ; 2.93,51.61 P13.2 ; P13.2 4.01,52.69 ; P13.2 5.09,51.61 ; P13.2 4.01,50.53 ; P1.GND2 138.75,78.99 ; P1.GND2 137.48,77.72 ; P1.GND2 140.02,77.72 ; P1.GND2 138.75,76.45 ; S12.3 46.86,106.68 ; S12.3 45.47,105.28 ; S12.3 45.47,108.08 ; S12.3 44.07,106.68 ; 19.6,16.74 M4.GND9 ; M4.GND9 20.68,17.82 ; M4.GND9 19.6,18.9 ; M4.GND9 18.52,17.82 ; J2.5 59.69,103.48 ; J2.5 58.42,102.21 ; J2.5 57.15,103.48 ; J2.5 58.42,104.75 ; 5.61,97.17 P8.1 ; P8.1 5.61,99.58 ; P8.1 6.82,98.37 ; P8.1 4.41,98.37 ; 33.65,32.07 M4.GND17 ; M4.GND17 35.55,32.07 ; M4.GND17 34.6,33.02 ; M4.GND15 28.42,32.07 ; M4.GND15 27.4,33.08 ; M4.GND15 27.4,31.05 ; M4.GND15 26.38,32.07 ; P13.8 5.09,59.23 ; P13.8 4.01,58.15 ; P13.8 2.93,59.23 ; P13.8 4.01,60.31
  BOTTOM w0.203: U22.C3 v5(73.76,18.08) U22.C2
  BOTTOM w0.229: D5.A 82.96,7.14 ; D4.A 80.82,7.14
  BOTTOM w0.254: v1(22.53,43.92) 22.83,43.61 U6.11 ; 141.64,55.88 141.45,55.69 U7.A3 141.09,56.11 141.09,56.12 ; v1(33.22,41.94) 32.97,42.19 U18.8 ; U5.8 41.86,42.19 v1(42.11,41.94) ; v1(40.31,43.92) 40.61,43.61 U5.11 ; U4.8 15.19,42.19 v1(15.44,41.94) ; v1(31.42,43.92) 31.72,43.61 U18.11 ; v1(24.33,41.94) 24.08,42.19 U6.8 ; v1(13.64,43.92) 13.94,43.61 U4.11
  BOTTOM w0.305: C122.1 v1(103.91,100.66) ; C120.1 v1(103.89,111.23) ; C119.2 91,118.15 ; C119.2 v1(90.5,118.77) ; C119.2 90.03,118.15
  BOTTOM w0.406: 83.5,5.27 P10.5 83.5,3.21 ; v2(71.88,16.5) C253.2
  BOTTOM w0.483: v7(117.96,39.48) 117.96,39.31 C71.2 ; C10.2 117.96,83.45 v7(117.96,83.61) ; 32.23,25.85 R60.2 32.72,25.19 ; C17.2 119.11,80.48 119.8,80.48 121.13,81.81 121.13,83.12 v7(120.85,83.4) ; C78.2 119.1,36.35 119.79,36.35 121.13,37.69 121.13,38.99 v7(120.85,39.26) ; R49.2 90.7,114.83
  BOTTOM w0.508: P1.GND4 140.02,86.42 ; P1.GND4 138.75,87.69 ; P1.GND4 138.75,85.15 ; P1.GND4 137.48,86.42 ; P2.GND3 146.42,42.28 ; P2.GND3 143.88,42.28 ; P2.GND3 145.15,41.01 ; P2.GND3 145.15,43.55 ; P13.8 4.01,60.31 ; P13.8 4.01,58.15 ; P13.8 2.93,59.23 ; P13.8 5.09,59.23 ; 37.1,31.05 M4.GND18 ; M4.GND18 36.08,32.07 ; M4.GND18 38.12,32.07 ; M4.GND18 37.1,33.08 ; 57.15,103.48 J2.5 ; J2.5 59.69,103.48 ; J2.5 58.42,102.21 ; J2.5 58.42,104.75 ; M4.GND15 28.42,32.07 ; M4.GND15 27.4,31.05 ; M4.GND15 27.4,33.08 ; M4.GND15 26.38,32.07 ; 130.76,107.29 J3.2 ; J3.2 132.03,108.56 ; J3.2 130.76,109.83 ; J3.2 129.49,108.56 ; M4.GND13 15.68,32.07 ; M4.GND13 14.6,30.99 ; M4.GND13 13.52,32.07 ; M4.GND13 14.6,33.15 ; M4.GND6 32.1,18.83 ; M4.GND6 33.12,17.82 ; M4.GND6 32.1,16.8 ; M4.GND6 31.08,17.82 ; 30.83,21.94 R62.2 31.33,21.41 ; 24.6,25.31 M4.GND19 ; M4.GND19 24.6,27.47 ; M4.GND19 23.52,26.39 ; M4.GND19 25.68,26.39 ; 119.33,103.48 J4.4 ; J4.4 120.6,102.21 ; J4.4 120.6,104.75 ; J4.4 121.87,103.48 ; 116.17,75.09 R6.2 ; R6.2 116.26,75.98 ; R6.2 R7.2 ; R6.2 117.05,75.19 ; 5.47,51.61 P13.1 ; P13.1 7.63,51.61 ; P13.1 6.55,52.69 ; P13.1 6.55,50.53 ; J1.4 85.09,103.48 ; J1.4 82.55,103.48 ; J1.4 83.82,104.75 ; J1.4 83.82,102.21 ; J3.5 130.76,104.75 ; J3.5 130.76,102.21 ; J3.5 132.03,103.48 ; J3.5 129.49,103.48 ; 37.72,42.21 R77.2 38.25,41.72 ; 48.43,54.18 P6.1 ; P6.1 50.58,54.18 ; P6.1 49.5,55.26 ; P6.1 49.5,53.1 ; 39.6,16.74 M4.GND4 ; M4.GND4 38.52,17.82 ; M4.GND4 40.68,17.82 ; M4.GND4 39.6,18.9 ; P13.6 4.01,57.77 ; P13.6 5.09,56.69 ; P13.6 2.93,56.69 ; P13.6 4.01,55.61 ; 62.23,103.48 J2.4 ; J2.4 63.5,104.75 ; J2.4 63.5,102.21 ; J2.4 64.77,103.48 ; 143.88,77.72 P1.GND1 ; P1.GND1 146.42,77.72 ; P1.GND1 145.15,76.45 ; P1.GND1 145.15,78.99 ; J1.2 80.01,108.56 ; J1.2 78.74,109.83 ; J1.2 77.47,108.56 ; J1.2 78.74,107.29 ; 96.32,113.87 U15.4 ; U15.4 99.01,113.87 ; U15.4 97.66,113.31 ; 58.42,107.29 J2.2 ; J2.2 58.42,109.83 ; J2.2 59.69,108.56 ; J2.2 57.15,108.56 ; M4.GND10 10.68,17.82 ; M4.GND10 8.52,17.82 ; M4.GND10 9.6,18.9 ; M4.GND10 9.6,16.74 ; P2.GND4 140.02,42.28 ; P2.GND4 138.75,41.01 ; P2.GND4 137.48,42.28 ; P2.GND4 138.75,43.55 ; 119.33,108.56 J4.3 ; J4.3 121.87,108.56 ; J4.3 120.6,109.83 ; J4.3 120.6,107.29 ; J1.3 85.09,108.56 ; J1.3 83.82,109.83 ; J1.3 83.82,107.29 ; J1.3 82.55,108.56 ; 11.05,41.28 R75.2 11.58,40.79 ; 41.7,19.12 M4.GND3 ; M4.GND3 41.7,21.15 ; M4.GND3 42.72,20.14 ; M4.GND3 40.68,20.14 ; 24.6,30.99 M4.GND14 ; M4.GND14 24.6,33.15 ; M4.GND14 23.52,32.07 ; M4.GND14 25.68,32.07 ; R21.2 116.71,45.13 ; R21.2 115.92,44.34 ; R21.2 115.82,45.23 ; R21.2 R20.2 ; J2.3 63.5,109.83 ; J2.3 64.77,108.56 ; J2.3 62.23,108.56 ; J2.3 63.5,107.29 ; M4.GND9 19.6,18.9 ; M4.GND9 20.68,17.82 ; M4.GND9 18.52,17.82 ; M4.GND9 19.6,16.74 ; J3.3 137.11,108.56 ; J3.3 135.84,109.83 ; J3.3 134.57,108.56 ; J3.3 135.84,107.29 ; 77.39,12.49 C260.2 ; C260.2 78.56,12.49 ; C260.2 77.98,13.04 ; R13.2 R12.2 ; R13.2 116.71,89.27 ; R13.2 115.82,89.37 ; R13.2 115.92,88.48 ; R12.2 116.78,87.62 ; R12.2 117.58,88.41 ; R12.2 117.67,87.52 ; Q1.3 54.42,57.41 ; Q1.3 55.12,56.26 ; Q1.3 53.72,56.26 ; Q1.3 54.42,55.1 ; 20.47,41.72 R79.2 19.94,42.21 ; J4.2 116.79,108.56 ; J4.2 115.52,107.29 ; J4.2 115.52,109.83 ; J4.2 114.25,108.56 ; 29.36,41.72 R230.2 28.83,42.21 ; J1.5 80.01,103.48 ; J1.5 78.74,104.75 ; J1.5 77.47,103.48 ; J1.5 78.74,102.21 ; 143.88,86.42 P1.GND3 ; P1.GND3 145.15,85.15 ; P1.GND3 146.42,86.42 ; P1.GND3 145.15,87.69 ; 29.6,16.74 M4.GND7 ; M4.GND7 28.52,17.82 ; M4.GND7 29.6,18.9 ; M4.GND7 30.68,17.82 ; 138.75,32.31 P2.GND2 ; P2.GND2 138.75,34.85 ; P2.GND2 137.48,33.58 ; P2.GND2 140.02,33.58 ; S12.3 45.47,108.08 ; S12.3 46.86,106.68 ; S12.3 44.07,106.68 ; S12.3 45.47,105.28 ; 26.38,17.82 M4.GND8 ; M4.GND8 27.4,18.83 ; M4.GND8 27.4,16.8 ; M4.GND8 28.42,17.82 ; M4.GND11 5.68,23.49 ; M4.GND11 3.52,23.49 ; M4.GND11 4.6,22.41 ; M4.GND11 4.6,24.57 ; 143.88,33.58 P2.GND1 ; P2.GND1 145.15,32.31 ; P2.GND1 146.42,33.58 ; P2.GND1 145.15,34.85 ; R15.2 117.92,31.92 ; R15.2 117.13,32.71 ; R15.2 R14.2 ; R15.2 118.02,32.81 ; 114.25,103.48 J4.5 ; J4.5 116.79,103.48 ; J4.5 115.52,102.21 ; J4.5 115.52,104.75 ; 135.84,102.21 J3.4 ; J3.4 134.57,103.48 ; J3.4 137.11,103.48 ; J3.4 135.84,104.75 ; 141.34,56.74 R84.2 ; R84.2 141.84,57.28 ; R84.2 141.34,57.81 ; M4.GND5 37.1,18.83 ; M4.GND5 37.1,16.8 ; M4.GND5 38.12,17.82 ; M4.GND5 36.08,17.82 ; 33.65,32.07 M4.GND17 ; M4.GND17 35.55,32.07 ; M4.GND17 34.6,33.02 ; 40.68,29.74 M4.GND1 ; M4.GND1 41.7,28.72 ; M4.GND1 41.7,30.75 ; 3.52,32.07 M4.GND12 ; M4.GND12 4.6,30.99 ; M4.GND12 5.68,32.07 ; M4.GND12 4.6,33.15 ; 24.6,19.91 M4.GND20 ; M4.GND20 24.6,22.07 ; M4.GND20 25.68,20.99 ; M4.GND20 23.52,20.99 ; P1.GND2 140.02,77.72 ; P1.GND2 138.75,76.45 ; P1.GND2 138.75,78.99 ; P1.GND2 137.48,77.72 ; 2.93,51.61 P13.2 ; P13.2 4.01,50.53 ; P13.2 4.01,52.69 ; P13.2 5.09,51.61 ; 98.18,111.43 C116.2 97.78,111.89 ; 4.01,53.07 P13.4 ; P13.4 4.01,55.23 ; P13.4 2.93,54.15 ; P13.4 5.09,54.15 ; R20.2 117.67,43.38 ; R20.2 117.58,44.27 ; R20.2 116.78,43.48 ; 31.08,32.07 M4.GND16 ; M4.GND16 32.1,31.05 ; M4.GND16 32.1,33.08 ; M4.GND16 33.12,32.07 ; 117.13,76.85 R7.2 ; R7.2 118.02,76.94 ; R7.2 117.92,76.05 ; R14.2 117.05,31.05 ; R14.2 116.26,31.84 ; R14.2 116.17,30.95 ; P8.1 5.61,99.58 ; P8.1 5.61,97.17 ; P8.1 4.41,98.37 ; P8.1 6.82,98.37 ; 78.54,8.96 R182.2 79.16,9.53
  BOTTOM w0.889: M4.GND2 42.72,24.94
  BOTTOM w1.016: FL1.6 35.99,106.45 ; FL1.6 34.03,105.04 ; FL1.6 35.99,103.63 ; 29.54,115.23 FL1.5 ; FL1.5 33.74,113.82 ; FL1.5 33.74,116.64 ; FL1.5 37.94,115.23 ; FL1.4 41.74,112.23 ; FL1.4 37.43,112.23 ; FL1.4 39.59,110.74 ; FL1.4 39.59,113.73
  vias: v1(1.7,60.72) v1(1.7,56.91) v1(1.7,53.1) v1(1.7,49.29) v1(1.74,87.63) v1(1.74,83.82) v1(1.74,80.01) v1(1.74,76.2) v1(1.74,72.39) v1(1.74,68.58) v1(1.74,64.77) v1(2.72,14.3) v1(2.72,10.49) v1(2.72,6.68) v1(2.81,118.6) v1(2.79,114.5) v1(2.79,110.69) v1(2.79,106.88) v1(2.79,103.07) v1(2.79,99.26) v1(2.79,91.64) v1(2.79,45.92) v1(2.79,42.11) v1(2.79,38.3) v1(2.79,34.49) v1(6.53,14.3) v1(6.53,10.49) v1(6.53,6.68) v1(6.53,2.87) v1(6.62,118.6) v1(6.6,110.69) v1(6.6,103.07) v1(6.6,45.92) v1(6.6,42.11) v1(6.6,38.3) v1(6.6,34.49) v1(6.87,91.29) v1(10.43,118.6) v1(10.41,114.5) v1(10.41,110.69) v1(10.41,106.88) v1(10.41,103.07) v1(10.41,99.26) v1(10.41,95.45) v1(10.41,61.16) v1(10.41,49.73) v1(10.41,42.11) v1(10.41,38.3) v1(10.41,34.49) v1(10.34,14.3) v1(10.34,10.49) v1(10.93,52.11) v1(10.84,41.27) v1(11.58,40.67) v1(12.55,36.45) v1(13.41,102.03) v1(13.46,97.13) v1(14.22,61.16) v1(14.22,49.73) v1(14.22,34.49) v1(14.15,14.3) v1(14.15,10.49) v1(14.15,6.68) v1(14.15,2.87) v1(14.24,118.6) v1(14.81,90.5) v1(15.32,39.73) v1(15.31,37.98) v1(16.09,36.26) v1(16.15,42.19) v1(16.33,40.64) v1(16.33,37.31) v1(16.74,81.64) v1(17.27,78.49) v1(17.25,75.34) v1(17.25,72.19) v1(17.6,46.56) v1(17.66,87.94) v1(17.69,84.77) v1(17.96,14.3) v1(17.96,10.49) v1(17.96,6.68) v1(17.96,2.87) v1(18.05,118.6) v1(18.03,61.16) v1(18.03,49.73) v1(18.03,34.49) v1(18.47,90.53) v1(18.67,63.83) v1(18.9,47.17) v1(19.31,85.03) v1(19.29,78.78) v1(19.3,76.91) v1(19.29,73.74) v1(19.29,70.79) v1(19.29,67.75) v1(19.29,53.58) v1(19.43,82.14) v1(19.81,46.35) v1(19.74,42.21) v1(19.91,59.13) v1(20.07,101.98) v1(20.09,97.54) v1(20.04,36.21) v1(20.66,39.25) v1(21.02,76.98) v1(21.31,54.43) v1(21.63,79.51) v1(21.69,90.04) v1(21.74,52.7) v1(21.78,44.66) v1(21.77,14.3) v1(21.77,10.49) v1(21.77,6.68) v1(21.77,2.87) v1(21.86,118.6) v1(21.84,61.16) v1(21.84,38.3) v1(21.84,34.49) v1(22.11,75.32) v1(22.11,72.31) v1(22.11,69.22) v1(22.15,55.14) v1(22.3,83.49) v1(22.25,66.07) v1(22.3,48.54) v1(22.35,86.46) v1(23.14,88.45) v1(23.79,36.21) v1(23.88,87.73) v1(24.21,39.73) v1(24.21,37.99) v1(24.61,66.14) v1(24.93,92.37) v1(25.07,42.16) v1(25.2,40.64) v1(25.22,37.34) v1(25.32,69.22) v1(25.25,54.2) v1(25.58,14.3) v1(25.58,10.49) v1(25.58,6.68) v1(25.58,2.87) v1(25.67,118.6) v1(25.65,34.49) v1(25.91,50.52) v1(26,84.3) v1(25.94,81.19) v1(26,78.7) v1(26.49,96.57) v1(26.49,46.56) v1(26.62,63.8) v1(26.9,100.36) v1(27.35,36.12) v1(27.71,57.35) v1(27.83,81.53) v1(27.79,47.14) v1(27.79,30.2) v1(28.14,97.54) v1(28.14,96.62) v1(28.17,95.66) v1(28.47,22.86) v1(28.6,91.85) v1(28.63,42.21) v1(28.7,46.28) v1(28.83,24.97) v1(29.26,93.35) v1(29.39,14.3) v1(29.39,10.49) v1(29.39,6.68) v1(29.39,2.87) v1(29.49,60.66) v1(29.46,34.49) v1(29.62,54.43) v1(29.62,46.58) v1(29.81,112.39) v1(29.81,111.63) v1(29.82,98.76) v1(29.82,94.39) v1(29.77,52.98) v1(29.92,21.13) v1(29.98,63.76) v1(29.99,55.83) v1(29.97,29.08) v1(30.18,100.36) v1(30.2,19.61) v1(30.44,88.21) v1(30.44,87.45) v1(30.44,86.69) v1(30.48,75.34) v1(30.57,112.39) v1(30.57,111.63) v1(30.58,80.24) v1(30.56,68.37) v1(30.66,117.63) v1(30.66,116.87) v1(30.76,48.13) v1(30.84,72.7) v1(31.01,45.42) v1(31.07,36.14) v1(31.2,88.21) v1(31.2,87.45) v1(31.2,86.69) v1(31.33,112.39) v1(31.33,111.63) v1(31.33,97.95) v1(31.34,95.87) v1(31.72,55.69) v1(31.92,63.08) v1(31.9,58.28) v1(31.9,40.21) v1(31.97,88.21) v1(31.97,87.45) v1(31.97,86.69) v1(31.96,61.53) v1(31.95,53.26) v1(32.1,112.39) v1(32.1,111.63) v1(32.18,94.18) v1(32.26,96.62) v1(32.92,110.48) v1(33.07,112.19) v1(33.17,117.19) v1(33.22,83.19) v1(33.2,14.3) v1(33.2,10.49) v1(33.2,6.68) v1(33.2,2.87) v1(33.29,118.6) v1(33.29,39.75) v1(33.29,37.99) v1(33.27,34.49) v1(33.36,80.24) v1(33.47,51.98) v1(33.99,42.14) v1(34.11,40.69) v1(34.11,37.36) v1(34.37,117.19) v1(34.56,64.42) v1(34.83,113.19) v1(34.95,112.25) v1(34.98,61.93) v1(35.41,103.43) v1(35.38,46.58) v1(35.51,106.68) v1(35.46,52.78) v1(35.46,52.02) v1(35.46,51.26) v1(35.46,50.5) v1(35.46,49.73) v1(35.74,83.19) v1(35.74,80.24) v1(36.22,52.78) v1(36.22,52.02) v1(36.22,51.26) v1(36.22,50.5) v1(36.22,49.73) v1(36.47,106.68) v1(36.58,103.43) v1(36.63,76.15) v1(36.63,75.16) v1(36.63,74.24) v1(36.63,73.28) v1(36.93,47.29) v1(36.98,52.78) v1(36.98,52.02) v1(36.98,51.26) v1(36.98,50.5) v1(36.98,49.73) v1(37.01,14.3) v1(37.01,10.49) v1(37.01,6.68) v1(37.01,2.87) v1(37.1,118.6) v1(37.08,34.49) v1(37.21,112.22) v1(37.24,54.76) v1(37.52,42.21) v1(37.82,53.8) v1(37.93,40.21) v1(38.17,115.98) v1(38.16,114.47) v1(38.23,96.37) v1(38.23,95.4) v1(38.83,110.51) v1(38.76,37.89) v1(38.92,60.39) v1(39.07,64.52) v1(39.04,46.28) v1(39.24,76.2) v1(39.24,74.9) v1(39.24,73.69) v1(39.6,113.95) v1(39.67,98.55) v1(39.65,93.22) v1(39.8,56.06) v1(40.34,110.52) v1(40.44,58.55) v1(40.59,102.18) v1(40.82,14.3) v1(40.82,10.49) v1(40.82,6.68) v1(40.82,2.87) v1(40.91,118.6) v1(40.89,114.5) v1(40.89,34.49) v1(41.02,54.1) v1(41.07,96.34) v1(41.07,95.43) v1(41.35,58.55) v1(41.97,112.22) v1(41.94,56.06) v1(42.14,53.16) v1(42.16,39.76) v1(42.16,37.99) v1(42.57,50.27) v1(42.88,42.14) v1(43.03,98.4) v1(42.95,60.38) v1(43,40.69) v1(43.03,37.36) v1(43.05,52.2) v1(43.05,49.1) v1(43.48,18.34) v1(43.61,25.2) v1(43.76,54.56) v1(43.95,57.61) v1(44.17,26.01) v1(44.17,24.36) v1(44.27,46.51) v1(44.53,32) v1(44.63,14.3) v1(44.63,10.49) v1(44.63,6.68) v1(44.63,2.87) v1(44.72,118.6) v1(44.73,102.16) v1(44.83,66.45) v1(44.81,56.77) v1(44.75,25.2) v1(45.19,95.89) v1(45.26,93.35) v1(45.26,90.83) v1(45.34,26.01) v1(45.34,24.36) v1(45.59,47.09) v1(45.77,57.61) v1(45.9,25.17) v1(45.97,52.6) v1(46.41,46.28) v1(46.48,92.08) v1(46.48,90.35) v1(46.51,86.08) v1(46.76,64.52) v1(46.86,77.52) v1(47.02,83.06) v1(46.94,54.58) v1(47.29,68.99) v1(47.47,98.43) v1(47.58,42.09) v1(47.65,48.21) v1(47.83,79.12) v1(47.78,61.16) v1(48,37.72) v1(48.34,93.04) v1(48.34,91.08) v1(48.53,118.6) v1(48.51,114.5) v1(48.51,110.69) v1(48.51,106.88) v1(48.51,103.07) v1(48.44,81.08) v1(48.44,14.3) v1(48.44,10.49) v1(48.44,2.87) v1(48.82,17.78) v1(48.84,79.12) v1(48.84,32.64) v1(48.99,40.13) v1(50.09,86.08) v1(50.11,35.71) v1(51.75,41.93) v1(51.84,98.45) v1(51.97,32.64) v1(51.97,25.15) v1(51.94,17.81) v1(51.94,14.76) v1(52.32,114.5) v1(52.32,110.69) v1(52.32,106.88) v1(52.32,103.07) v1(52.3,51.05) v1(52.25,10.49) v1(52.25,2.87) v1(52.34,118.6) v1(52.43,77.32) v1(52.4,72.39) v1(52.4,66.6) v1(52.4,53.98) v1(52.76,62.28) v1(52.83,56.79) v1(53.39,39.07) v1(53.49,56.03) v1(53.57,59.54) v1(55.22,101.88) v1(55.37,81.66) v1(55.37,76.02) v1(55.37,70.54) v1(55.37,64.77) v1(55.37,51) v1(55.37,45.72) v1(56.15,118.6) v1(56.13,114.5) v1(56.31,30.84) v1(56.31,26.95) v1(56.31,24.33) v1(56.39,34.7) v1(56.34,20.42) v1(56.52,106.1) v1(56.52,17.2) v1(56.67,92.41) v1(56.67,39.85) v1(56.74,96.77) v1(56.9,64.77) v1(56.9,54.1) v1(56.9,51) v1(56.9,45.72) v1(56.87,15.04) v1(56.84,2.25) v1(57.4,69.14) v1(57.61,81.28) v1(57.61,77.47) v1(57.61,73.66) v1(58.16,16.61) v1(58.42,23.06) v1(58.82,15.43) v1(58.93,12.83) v1(58.93,12.12) v1(59.03,35.2) v1(59.13,32.08) v1(59.1,2.24) v1(59.46,92.41) v1(59.84,8.33) v1(59.96,118.6) v1(59.94,114.5) v1(60.05,62.01) v1(60.06,58.43) v1(60.17,20.83) v1(60.76,101.96) v1(60.83,46.51) v1(60.83,41.58) v1(60.86,51.26) v1(61.01,110.62) v1(61.19,37.29) v1(61.17,33.91) v1(61.19,31.39) v1(61.42,81.28) v1(61.42,77.47) v1(61.42,73.66) v1(61.45,52.23) v1(61.6,28.42) v1(61.98,17.75) v1(62.48,3.3) v1(63.2,98.37) v1(63.46,69.83) v1(63.45,19.46) v1(63.7,7.92) v1(63.75,118.31) v1(63.75,114.5) v1(64.19,20.16) v1(65.23,81.28) v1(65.23,77.47) v1(65.96,3.33) v1(66.29,89.33) v1(66.4,100.15) v1(66.7,64.8) v1(66.67,61.98) v1(66.67,58.17) v1(66.67,54.36) v1(66.67,50.55) v1(66.67,46.74) v1(66.67,42.93) v1(66.67,35.31) v1(66.67,31.5) v1(67.11,24.03) v1(67.56,118.31) v1(67.56,114.5) v1(67.82,110.64) v1(68.05,105.13) v1(68.63,102.74) v1(68.55,74.43) v1(69.09,89.84) v1(69.04,81.28) v1(69.13,17.88) v1(69.44,7.9) v1(69.65,64.69) v1(69.85,21.77) v1(69.95,18.69) v1(69.95,17.88) v1(70.05,1.83) v1(70.59,89.33) v1(70.54,69.34) v1(71.25,3.2) v1(71.37,118.31) v1(71.37,114.5) v1(71.35,82.91) v1(72.16,103.2) v1(72.44,108.71) v1(72.47,1.85) v1(72.69,106.64) v1(72.69,4.85) v1(73.34,79.65) v1(73.34,68.19) v1(73.62,106.02) v1(73.96,85.42) v1(74.35,1.24) v1(74.7,3.78) v1(75.18,118.31) v1(75.18,114.5) v1(75.21,102.79) v1(75.67,8.41) v1(75.92,4.85) v1(76.48,75.29) v1(76.48,12.88) v1(76.63,15.77) v1(77.06,72.05) v1(77.14,3.78) v1(77.5,89.08) v1(77.98,13.26) v1(78.52,84.62) v1(78.54,8.76) v1(78.82,14.68) v1(78.79,12.67) v1(78.84,90.7) v1(78.99,118.31) v1(78.99,114.5) v1(79.76,8.59) v1(80.11,7.77) v1(80.21,3.4) v1(80.37,13.72) v1(80.79,91.91) v1(80.82,7.77) v1(81.23,109.96) v1(81.14,12.22) v1(81.14,11.46) v1(81.73,80.01) v1(81.76,76.3) v1(81.9,12.22) v1(81.9,11.46) v1(82.05,86.4) v1(82.66,12.22) v1(82.66,11.46) v1(82.8,118.31) v1(82.8,114.5) v1(82.96,7.77) v1(83.85,5.28) v1(84.23,106.05) v1(84.18,3.4) v1(84.39,79.42) v1(84.77,11.46) v1(85.02,16.99) v1(85.6,86.82) v1(85.67,16.28) v1(86.26,9.04) v1(86.26,5.66) v1(86.66,11.68) v1(87.02,109.47) v1(86.97,102.74) v1(87,88.09) v1(87.81,12.93) v1(87.99,1.35) v1(88.11,3.89) v1(88.37,16.71) v1(88.59,12.92) v1(88.77,113.23) v1(89.94,5.69) v1(90.14,12.19) v1(90.63,114.73) v1(90.58,111.73) v1(90.65,1.35) v1(91.08,107.04) v1(91.14,112.29) v1(91.21,103.38) v1(93.68,11.89) v1(93.92,91.9) v1(93.88,19.13) v1(94.26,113.21) v1(94.57,107.55) v1(94.57,106.79) v1(94.57,106.02) v1(94.57,105.26) v1(94.57,104.5) v1(95.1,117.04) v1(95.33,107.55) v1(95.33,106.79) v1(95.33,106.02) v1(95.33,105.26) v1(95.33,104.5) v1(95.33,103.74) v1(96.1,107.55) v1(96.1,106.79) v1(96.1,106.02) v1(96.1,105.26) v1(96.1,104.5) v1(96.1,103.74) v1(96.06,19.13) v1(96.47,5.46) v1(96.47,1.75) v1(96.61,24) v1(96.61,23.21) v1(96.86,107.55) v1(96.86,106.79) v1(96.86,106.02) v1(96.86,105.26) v1(96.86,104.5) v1(96.86,103.74) v1(96.87,22.5) v1(97.13,9.04) v1(97.26,12.55) v1(97.62,107.55) v1(97.62,106.79) v1(97.62,106.02) v1(97.62,105.26) v1(97.62,104.5) v1(97.62,103.74) v1(97.59,91.35) v1(97.57,23.64) v1(98.43,111.43) v1(98.38,107.55) v1(98.38,106.79) v1(98.38,106.02) v1(98.38,105.26) v1(98.38,104.5) v1(98.38,103.74) v1(99.06,13.06) v1(99.21,113.87) v1(99.14,110.9) v1(99.14,107.55) v1(99.14,106.79) v1(99.14,106.02) v1(99.14,105.26) v1(99.54,100.36) v1(99.95,8.81) v1(100.13,91.35) v1(100.33,109.45) v1(100.33,102.62) v1(100.41,117.83) v1(100.41,115.39) v1(100.41,2.01) v1(100.66,12.37) v1(101.19,24.56) v1(101.27,111.35) v1(101.35,100.71) v1(101.9,19) v1(101.98,13.74) v1(102.41,107.21) v1(102.67,91.36) v1(103.02,106.53) v1(103.33,20.14) v1(103.25,13.84) v1(103.4,117.04) v1(103.35,23.06) v1(103.45,113.72) v1(104.09,47.75) v1(104.5,4.6) v1(104.85,8.81) v1(105.03,1.04) v1(106.3,3.56) v1(106.38,96.6) v1(106.5,12.67) v1(106.86,21.03) v1(106.86,15.62) v1(107.09,50.65) v1(107.21,106.3) v1(107.24,96.61) v1(107.31,72.14) v1(107.33,31.93) v1(107.37,27.71) v1(107.45,99.66) v1(107.46,98.83) v1(107.55,82.04) v1(107.55,37.91) v1(107.71,69.21) v1(107.92,71.48) v1(107.87,27.2) v1(108.03,14.78) v1(108.09,82.58) v1(108.09,81.5) v1(108.09,38.44) v1(108.09,37.37) v1(108.25,25.35) v1(108.63,83.12) v1(108.63,82.04) v1(108.63,80.97) v1(108.63,38.98) v1(108.63,37.91) v1(108.63,36.83) v1(108.74,111.1) v1(108.99,115.67) v1(109.14,114.22) v1(109.17,83.66) v1(109.17,82.58) v1(109.17,81.5) v1(109.17,80.43) v1(109.17,39.52) v1(109.17,38.44) v1(109.17,37.37) v1(109.17,36.29) v1(109.19,15.62) v1(109.25,49.12) v1(109.5,100.47) v1(109.63,19) v1(109.71,84.2) v1(109.71,83.12) v1(109.71,82.04) v1(109.71,80.97) v1(109.71,79.89) v1(109.71,40.06) v1(109.71,38.98) v1(109.71,37.91) v1(109.71,36.83) v1(109.71,35.75) v1(109.83,23.9) v1(109.88,113.49) v1(109.85,48.49) v1(110.03,1.04) v1(110.12,93.2) v1(110.04,47.12) v1(110.23,96.87) v1(110.23,95.99) v1(110.24,84.74) v1(110.24,83.66) v1(110.24,82.58) v1(110.24,81.5) v1(110.24,80.43) v1(110.24,53.59) v1(110.24,40.6) v1(110.24,39.52) v1(110.24,38.44) v1(110.24,37.37) v1(110.24,36.29) v1(110.59,26.24) v1(110.63,46.53) v1(110.78,83.12) v1(110.78,82.04) v1(110.78,80.97) v1(110.78,38.98) v1(110.78,37.91) v1(110.78,36.83) v1(110.82,13.92) v1(111.09,92.29) v1(111.1,91.47) v1(111.05,21.01) v1(111.32,82.58) v1(111.32,81.5) v1(111.32,38.44) v1(111.32,37.37) v1(111.25,6.58) v1(111.25,3.53) v1(111.43,12.17) v1(111.46,103.28) v1(111.56,114.78) v1(111.58,51) v1(111.68,18.92) v1(111.86,82.04) v1(111.86,37.91) v1(112.12,111.05) v1(112.12,108.08) v1(112.09,47.8) v1(112.57,99.7) v1(112.73,45.44) v1(113.03,57.15) v1(113.08,117.58) v1(113.06,114.78) v1(113.31,93.07) v1(113.87,74.73) v1(114.3,114.78) v1(114.48,111.94) v1(114.55,15.62) v1(114.96,1.07) v1(115.11,4.6) v1(115.14,7.75) v1(115.39,20.88) v1(115.44,67.23) v1(115.72,14.78) v1(115.91,92.58) v1(116,60.07) v1(115.95,27.33) v1(116.05,51.97) v1(116.36,10.95) v1(116.61,112.4) v1(116.89,89.43) v1(116.92,55.55) v1(116.87,45.29) v1(117.12,71.27) v1(117.32,115.37) v1(117.32,19) v1(117.38,31.09) v1(117.48,49.36) v1(117.51,46.43) v1(117.7,118.16) v1(117.68,114.4) v1(117.68,113.64) v1(117.68,112.88) v1(117.73,88.57) v1(117.73,44.42) v1(117.66,23.47) v1(117.91,75.21) v1(117.89,31.59) v1(117.96,111.33) v1(117.96,45.57) v1(118.44,114.4) v1(118.44,113.64) v1(118.44,112.88) v1(118.72,3.45) v1(118.82,115.37) v1(118.77,68.48) v1(118.77,66.62) v1(118.96,61.23) v1(119,57.58) v1(119.02,13.56) v1(119.2,99.26) v1(119.23,94.21) v1(119.23,64.62) v1(119.15,34.26) v1(119.43,8.64) v1(119.56,78.54) v1(119.81,95.58) v1(119.94,98.55) v1(119.94,97.71) v1(120.04,86.18) v1(120.22,90.7) v1(120.14,55.19) v1(120.5,1.07) v1(120.62,52.65) v1(120.55,20.27) v1(120.73,96.98) v1(120.73,96.14) v1(120.7,69.24) v1(120.73,51.16) v1(120.8,33.32) v1(120.8,4.88) v1(120.88,95.3) v1(120.88,94.41) v1(120.93,86.18) v1(120.98,110.08) v1(121.16,70.54) v1(121.26,67.95) v1(121.28,63.98) v1(121.26,28.78) v1(121.39,93.6) v1(121.39,26.39) v1(121.49,91.52) v1(121.44,49.35) v1(121.56,47.29) v1(121.57,23.72) v1(121.95,40.03) v1(122.07,81.13) v1(122.22,15.62) v1(122.33,83.9) v1(122.35,31.5) v1(122.45,72.62) v1(122.82,61.27) v1(122.81,57.58) v1(122.86,75.51) v1(122.91,12.83) v1(122.94,113.41) v1(122.94,112.29) v1(123.06,5.23) v1(123.24,82.09) v1(123.42,14.78) v1(124,103.51) v1(123.98,37.74) v1(124.33,8.69) v1(124.56,15.62) v1(124.79,117.7) v1(124.79,113.89) v1(124.79,110.08) v1(125.15,5.64) v1(125.4,1.07) v1(125.53,49.43) v1(125.45,12.83) v1(125.65,107.62) v1(126.03,82.09) v1(126.09,30.2) v1(126.62,61.39) v1(126.62,57.58) v1(126.8,100.89) v1(126.8,70.61) v1(127.36,103.53) v1(127.99,12.83) v1(128.27,58.42) v1(128.35,74.37) v1(128.6,117.7) v1(128.6,113.89) v1(128.6,110.08) v1(128.57,37.9) v1(129.08,6.53) v1(129.18,100.86) v1(129.97,17.55) v1(130.12,66.73) v1(130.18,98.73) v1(130.15,26.42) v1(130.3,82.04) v1(130.25,76.89) v1(130.33,52.37) v1(130.25,45.47) v1(130.53,70.38) v1(130.53,12.83) v1(130.51,1.07) v1(130.61,60.12) v1(130.78,15.62) v1(132.08,10.11) v1(132.41,117.7) v1(132.41,113.89) v1(132.41,110.08) v1(132.63,72.44) v1(132.7,91.7) v1(132.7,47.5) v1(132.7,28.32) v1(132.64,18.77) v1(133.07,3.15) v1(133.27,24.61) v1(133.39,91.7) v1(133.37,72.44) v1(133.43,68.81) v1(133.38,47.49) v1(133.38,28.32) v1(133.63,37.9) v1(133.91,76.61) v1(133.91,6.53) v1(134.12,91.72) v1(134.12,72.45) v1(134.05,47.5) v1(134.05,28.32) v1(134.19,95.22) v1(134.32,51.28) v1(134.37,43.76) v1(134.39,32.46) v1(134.82,82.19) v1(134.85,87.91) v1(135.21,60.64) v1(135.21,59.87) v1(135.21,59.11) v1(135.55,19.53) v1(135.53,18.67) v1(135.79,17.79) v1(135.74,1.07) v1(135.97,60.64) v1(135.97,59.11) v1(136.07,16.76) v1(136.22,117.7) v1(136.22,113.89) v1(136.22,110.08) v1(136.22,106.27) v1(136.22,68.17) v1(136.47,95) v1(136.73,60.64) v1(136.73,59.87) v1(136.73,59.11) v1(137.2,101.83) v1(137.16,15.49) v1(137.57,95) v1(137.67,26.49) v1(137.88,103.49) v1(137.92,90.73) v1(138.53,99.03) v1(138.91,19.08) v1(138.96,63.02) v1(138.94,22.23) v1(139.12,96.22) v1(139.06,11.38) v1(139.04,7.54) v1(139.17,104.62) v1(139.24,2.31) v1(140.03,117.7) v1(140.03,113.89) v1(140.03,110.08) v1(140.03,106.27) v1(140.03,68.17) v1(140.03,52.93) v1(140.03,49.12) v1(140.13,26.47) v1(140.12,21.44) v1(140.12,20.68) v1(140.12,19.91) v1(140.33,103.51) v1(140.33,98.48) v1(140.33,97.72) v1(140.33,96.96) v1(140.34,92.01) v1(140.64,63.02) v1(140.88,21.44) v1(140.88,20.68) v1(140.88,19.91) v1(141.01,64.2) v1(141.1,98.48) v1(141.1,97.72) v1(141.1,96.96) v1(141.33,27.58) v1(141.35,67.46) v1(141.35,65.99) v1(141.5,18.06) v1(141.55,104.62) v1(141.59,56.18) v1(141.73,95) v1(141.64,21.44) v1(141.64,20.68) v1(141.64,19.91) v1(141.86,98.48) v1(141.86,97.72) v1(141.86,96.96) v1(141.92,28.25) v1(141.94,90.83) v1(142.09,100.41) v1(142.47,22.66) v1(142.58,26.46) v1(142.8,91.95) v1(142.75,66.37) v1(142.75,56.9) v1(142.85,12.55) v1(143.08,15.49) v1(143.05,6.12) v1(143.05,2.64) v1(143.56,65.74) v1(143.56,56.29) v1(143.84,117.7) v1(143.84,113.89) v1(143.84,110.08) v1(143.84,106.27) v1(143.84,71.98) v1(143.84,68.17) v1(143.84,52.93) v1(143.84,49.12) v1(144.17,16.76) v1(144.53,20.78) v1(144.58,15.74) v1(144.81,17.63) v1(144.78,7.65) v1(144.88,97.94) v1(144.98,94.46) v1(145.26,30.68) v1(146.56,93.37) v1(146.79,100.05) v1(147.52,37.97) v1(147.65,113.89) v1(147.65,110.08) v1(147.65,106.27) v1(147.65,102.46) v1(147.65,91.03) v1(147.65,87.22) v1(147.65,83.41) v1(147.65,79.6) v1(147.65,75.79) v1(147.65,71.98) v1(147.65,68.17) v1(147.65,64.36) v1(147.65,56.74) v1(147.65,52.93) v1(147.65,49.12) v1(147.65,45.31) v1(147.7,41.12) v1(147.65,34.98) v1(147.68,30.89) v1(147.65,27.33) v1(147.65,23.77) v1(147.78,21.21) v1(147.78,18.67) v1(147.8,15.88) v1(147.8,12.45) v1(148.03,98.22) v1(148.06,95.68) v1(148.06,82.04) v2(68.71,56.2) v2(68.71,50.26) v2(68.71,43.76) v2(68.73,38.58) v2(68.73,34.36) v2(68.73,30.06) v2(68.75,61.67) v2(70.82,38.68) v2(70.86,35.09) v2(71.08,42.19) v2(71.19,61.89) v2(71.13,58.49) v2(71.17,52.26) v2(71.17,45.86) v2(73,34.07) v2(73.19,31.51) v2(73.64,65.16) v2(73.83,53.14) v2(73.86,48.33) v2(73.89,44.76) v2(73.87,38.66) v2(74.02,61.82) v2(73.96,57.47) v2(73.96,41.22) v2(74.42,30.02) v2(74.78,23.44) v2(76.15,64.96) v2(76.57,68.04) v2(76.85,48.04) v2(77.08,61.79) v2(77.59,56.98) v2(77.65,52.12) v2(78.65,67.46) v2(79.02,70.49) v2(79.01,64.94) v2(79.34,31.7) v2(79.52,56.91) v2(79.5,50.35) v2(79.49,46.78) v2(79.43,42.01) v2(79.5,38.66) v2(79.49,35.53) v2(79.67,60.78) v2(81.23,43.44) v2(81.23,38.81) v2(81.23,36.87) v2(81.29,34.19) v2(81.59,61.87) v2(81.7,67.71) v2(81.76,73.25) v2(81.74,70.5) v2(81.79,64.73) v2(81.73,52.49) v2(82.58,31.95) v2(82.54,31.23) v2(82.95,44.86) v2(82.95,36.87) v2(83.33,25.15) v2(83.73,54.33) v2(83.78,58.29) v2(83.75,50.46) v2(83.95,30.02) v2(84.23,34.37) v2(84.23,33.71) v2(84.23,33.01) v2(84.53,70.51) v2(84.68,36.96) v2(84.66,34.82) v2(84.9,56.41) v2(84.93,67.51) v2(85.2,74) v2(85.19,47.4) v2(85.15,45.3) v2(85.17,31.31) v2(85.82,77.44) v2(87.42,45.4) v2(87.48,42.94) v2(87.45,31.15) v2(87.45,27.68) v2(87.45,23.92) v2(87.56,50.28) v2(88.05,74) v2(88.07,70.65) v2(88.13,47.39) v2(88.44,62.2) v2(88.56,77.32) v2(88.67,80.16) v2(89.18,65.08) v2(89.39,60.35) v2(89.51,30.77) v2(89.51,30.02) v2(90.01,56.87) v2(89.98,45.39) v2(90.29,52.76) v2(90.61,49.79) v2(90.64,62.18) v2(90.99,66.45) v2(91.37,74.63) v2(91.57,68.82) v2(91.69,71.93) v2(91.79,47.4) v2(91.81,37.58) v2(91.81,35.44) v2(92.23,25.34) v2(92.23,24.63) v2(92.23,23) v2(92.23,21.34) v2(92.25,78.16) v2(92.62,43.29) v2(92.69,59.37) v2(92.68,39.69) v2(93.41,45.41) v2(93.57,52.76) v2(93.88,69.71) v2(93.92,57.37) v2(94.04,66.04) v2(94.22,85.68) v2(94.21,49.89) v2(94.57,62.38) v2(94.72,83.55) v2(94.65,75.43) v2(95.12,72.72) v2(95.28,47.41) v2(95.74,78.99) v2(96.24,82.19) v2(96.81,56.02) v2(97.04,52.53) v2(97.51,49.58) v2(97.76,98.27) v2(97.75,78.53) v2(97.84,89.37) v2(98.11,73.02) v2(98.04,68.78) v2(98.16,64.76) v2(98.14,62.06) v2(98.39,76.61) v2(98.67,24.41) v2(98.79,87.59) v2(99.77,85.68) v2(99.75,83.04) v2(99.82,55.44) v2(99.91,75.48) v2(99.86,59.03) v2(100.1,80.87) v2(100.13,39.8) v2(100.23,45.49) v2(100.6,52.65) v2(100.64,37.82) v2(100.66,32.39) v2(100.74,78.81) v2(101,35.41) v2(101.31,81.53) v2(101.41,69.12) v2(101.49,79.68) v2(101.44,61.61) v2(101.5,43.29) v2(101.51,41.15) v2(101.56,64.76) v2(101.68,73.88) v2(101.64,46.22) v2(101.93,87.93) v2(101.93,86.2) v2(101.96,77.59) v2(102.02,36.49) v2(102.05,33.67) v2(102.2,84.37) v2(102.2,82.64) v2(102.29,40.67) v2(102.41,34.29) v2(102.41,30.67) v2(102.82,78.34) v2(102.92,86.17) v2(103.14,87.94) v2(103.15,58.86) v2(103.24,76.19) v2(103.33,32.42) v2(103.28,25.13) v2(103.46,55.54) v2(103.91,84.42) v2(103.92,37.25) v2(103.92,32.76) v2(104.04,77.11) v2(104.2,41.32) v2(104.35,89.3) v2(104.4,69.04) v2(104.47,74.96) v2(104.49,72.78) v2(104.61,64.64) v2(104.69,61.62) v2(104.84,30.9) v2(105.67,88.02) v2(106.24,43.47) v2(106.72,76.23) v2(106.75,43.96) v2(106.74,32.23) v2(106.93,89.28) v2(107.05,59.2) v2(107.19,45.06) v2(107.29,75) v2(107.44,88.98) v2(107.7,77.95) v2(107.71,76.15) v2(107.77,33.94) v2(107.91,61.78) v2(108.13,92.79) v2(108.58,93.21) v2(108.61,43.66) v2(108.81,87.66) v2(110.01,90.75) v2(110.59,90.17) v2(110.64,89.36) v3(73.07,23.17) v3(76.68,24.31) v3(79.83,25.01) v3(81.64,28.83) v3(83.72,27.71) v3(85.29,25.34) v3(87.76,25.25) v3(92.23,27.66) v3(94.34,16.99) v3(94.79,32.39) v3(96.04,34.54) v3(99.09,16.36) v3(109.38,32.06) v3(114.05,83.64) v3(114.05,39.52) v3(115.29,82.45) v3(115.29,38.3) v3(120.95,88.6) v3(120.95,44.81) v3(122,44.07) v3(122,43.08) v3(122,41.17) v3(122,36.88) v3(122,35.89) v3(122.12,87.88) v3(122.12,86.84) v3(122.1,77.22) v3(122.1,76.2) v3(122.1,39.3) v3(122.1,38.27) v3(122.12,32.44) v3(122.2,84.99) v3(122.17,82.63) v3(122.15,79.73) v3(122.91,43.61) v3(122.94,40.59) v3(122.94,38.79) v3(122.94,36.35) v3(123.16,87.43) v3(123.22,76.71) v3(123.27,84.43) v3(123.29,80.49) v4(73.07,23.17) v4(76.68,24.31) v4(79.83,25.01) v4(81.64,28.83) v4(83.72,27.71) v7(113.22,29.09) v7(113.63,32.01) v7(120.73,50.27) v7(120.8,32.54) v7(121.01,77.32) v7(121.01,76.53) v7(121.31,88.44) v7(121.31,87.78) v7(121.28,44.4) v7(121.28,43.81)
